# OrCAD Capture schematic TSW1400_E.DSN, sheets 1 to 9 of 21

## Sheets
1 BLOCK DIAGRAM: title: BLOCK DIAGRAM; rev: E; note: SCH, TSW1400 EVM
2 BUTTON, SWITCH, LEDS: size B; title: SWITCHES, LEDS, BUTTONS
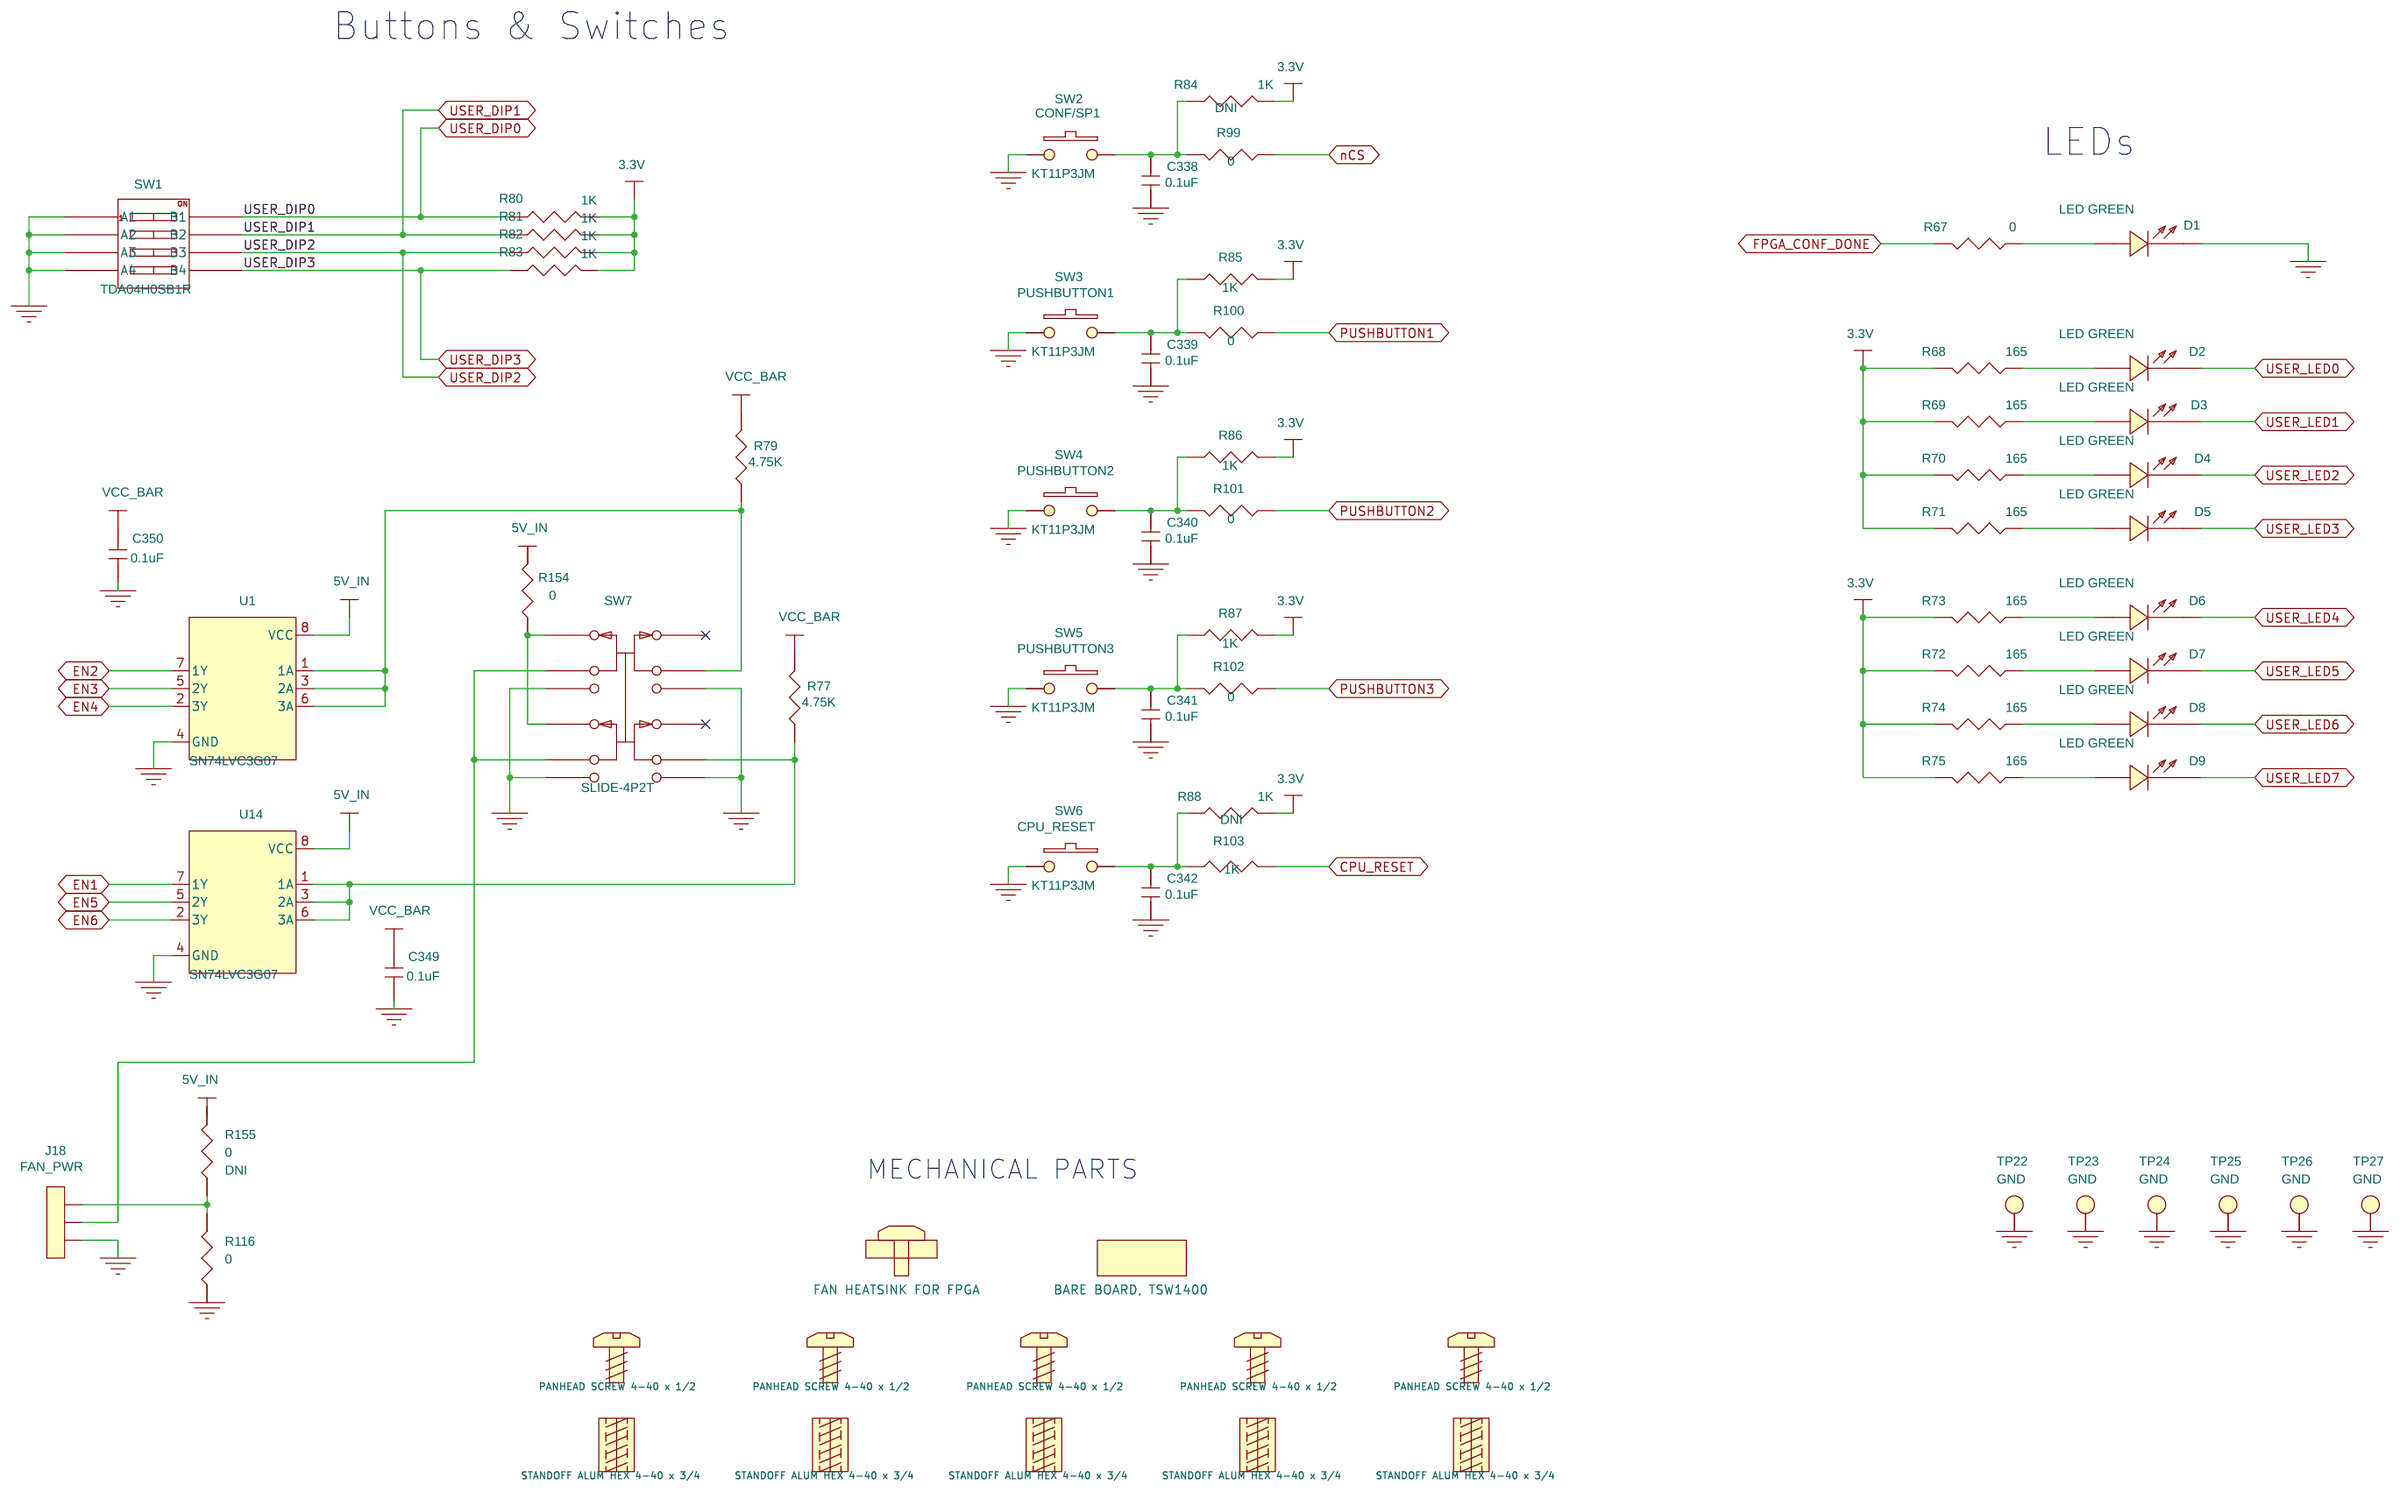
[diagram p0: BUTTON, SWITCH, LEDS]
3 ADC Interface, CMOS Header: size B; title: ADC INTERFACE & CMOS HEADER
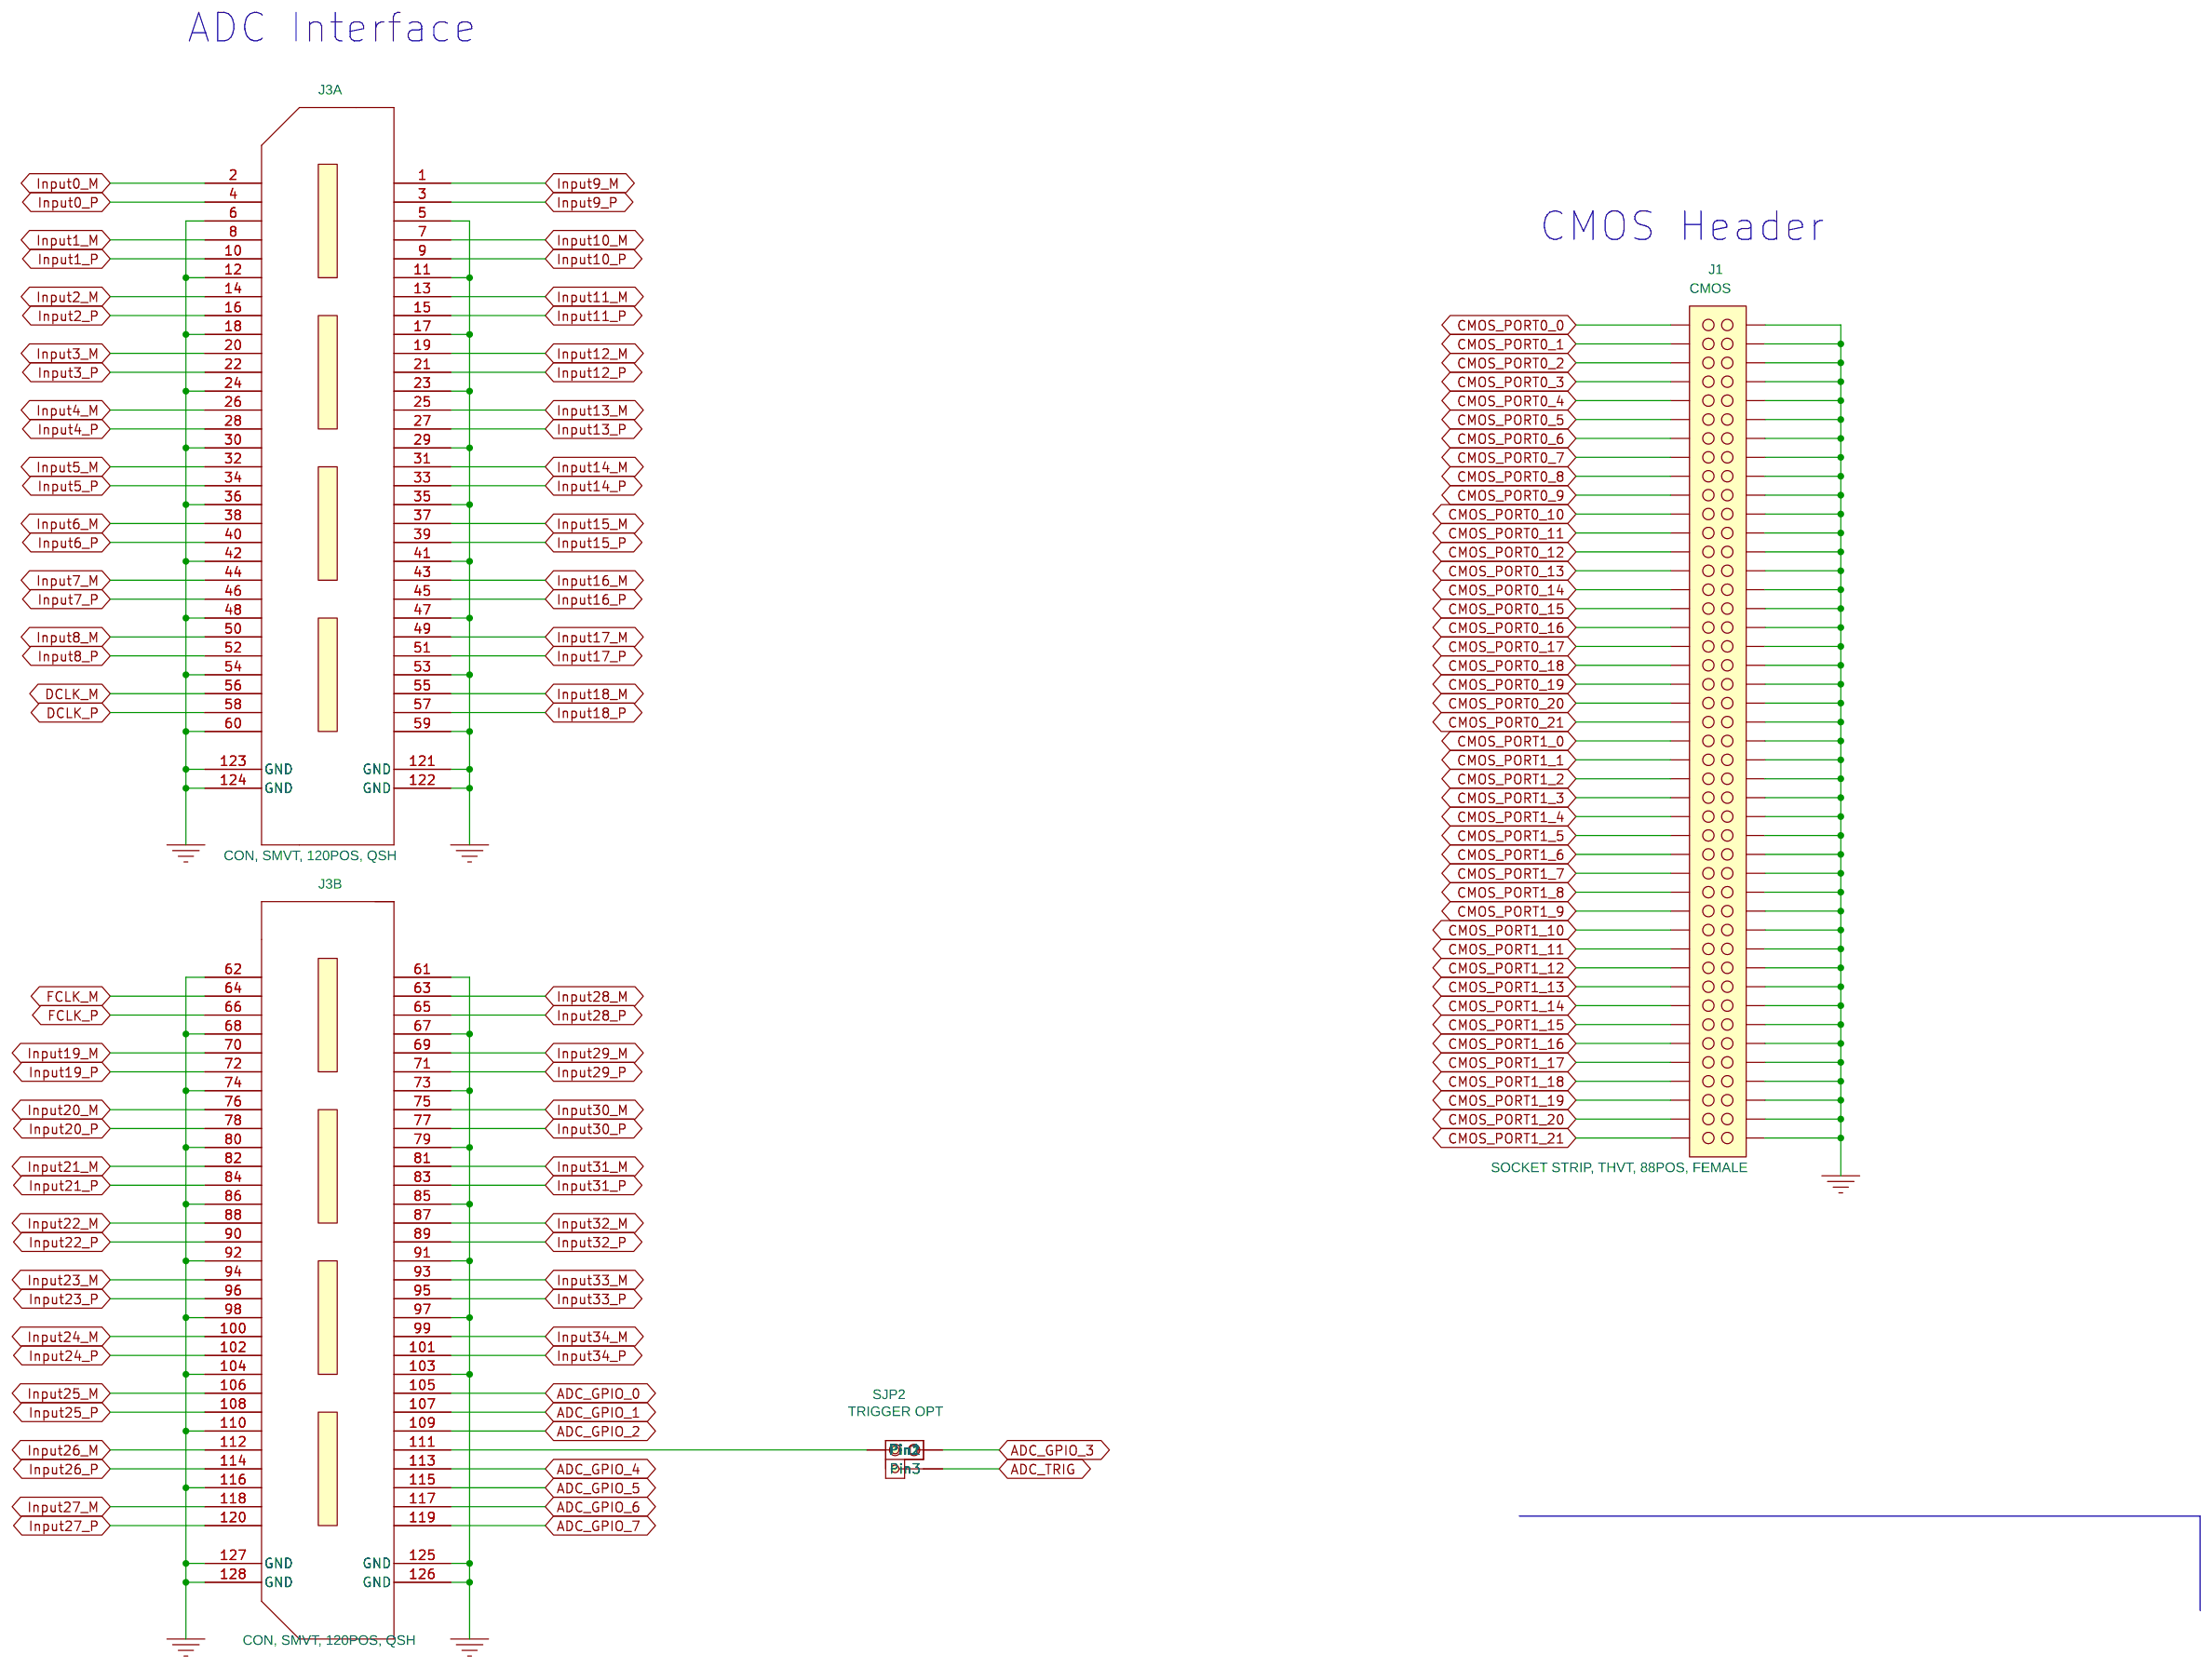
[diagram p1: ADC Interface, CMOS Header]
4 DAC Interface: size B; title: DAC Interface
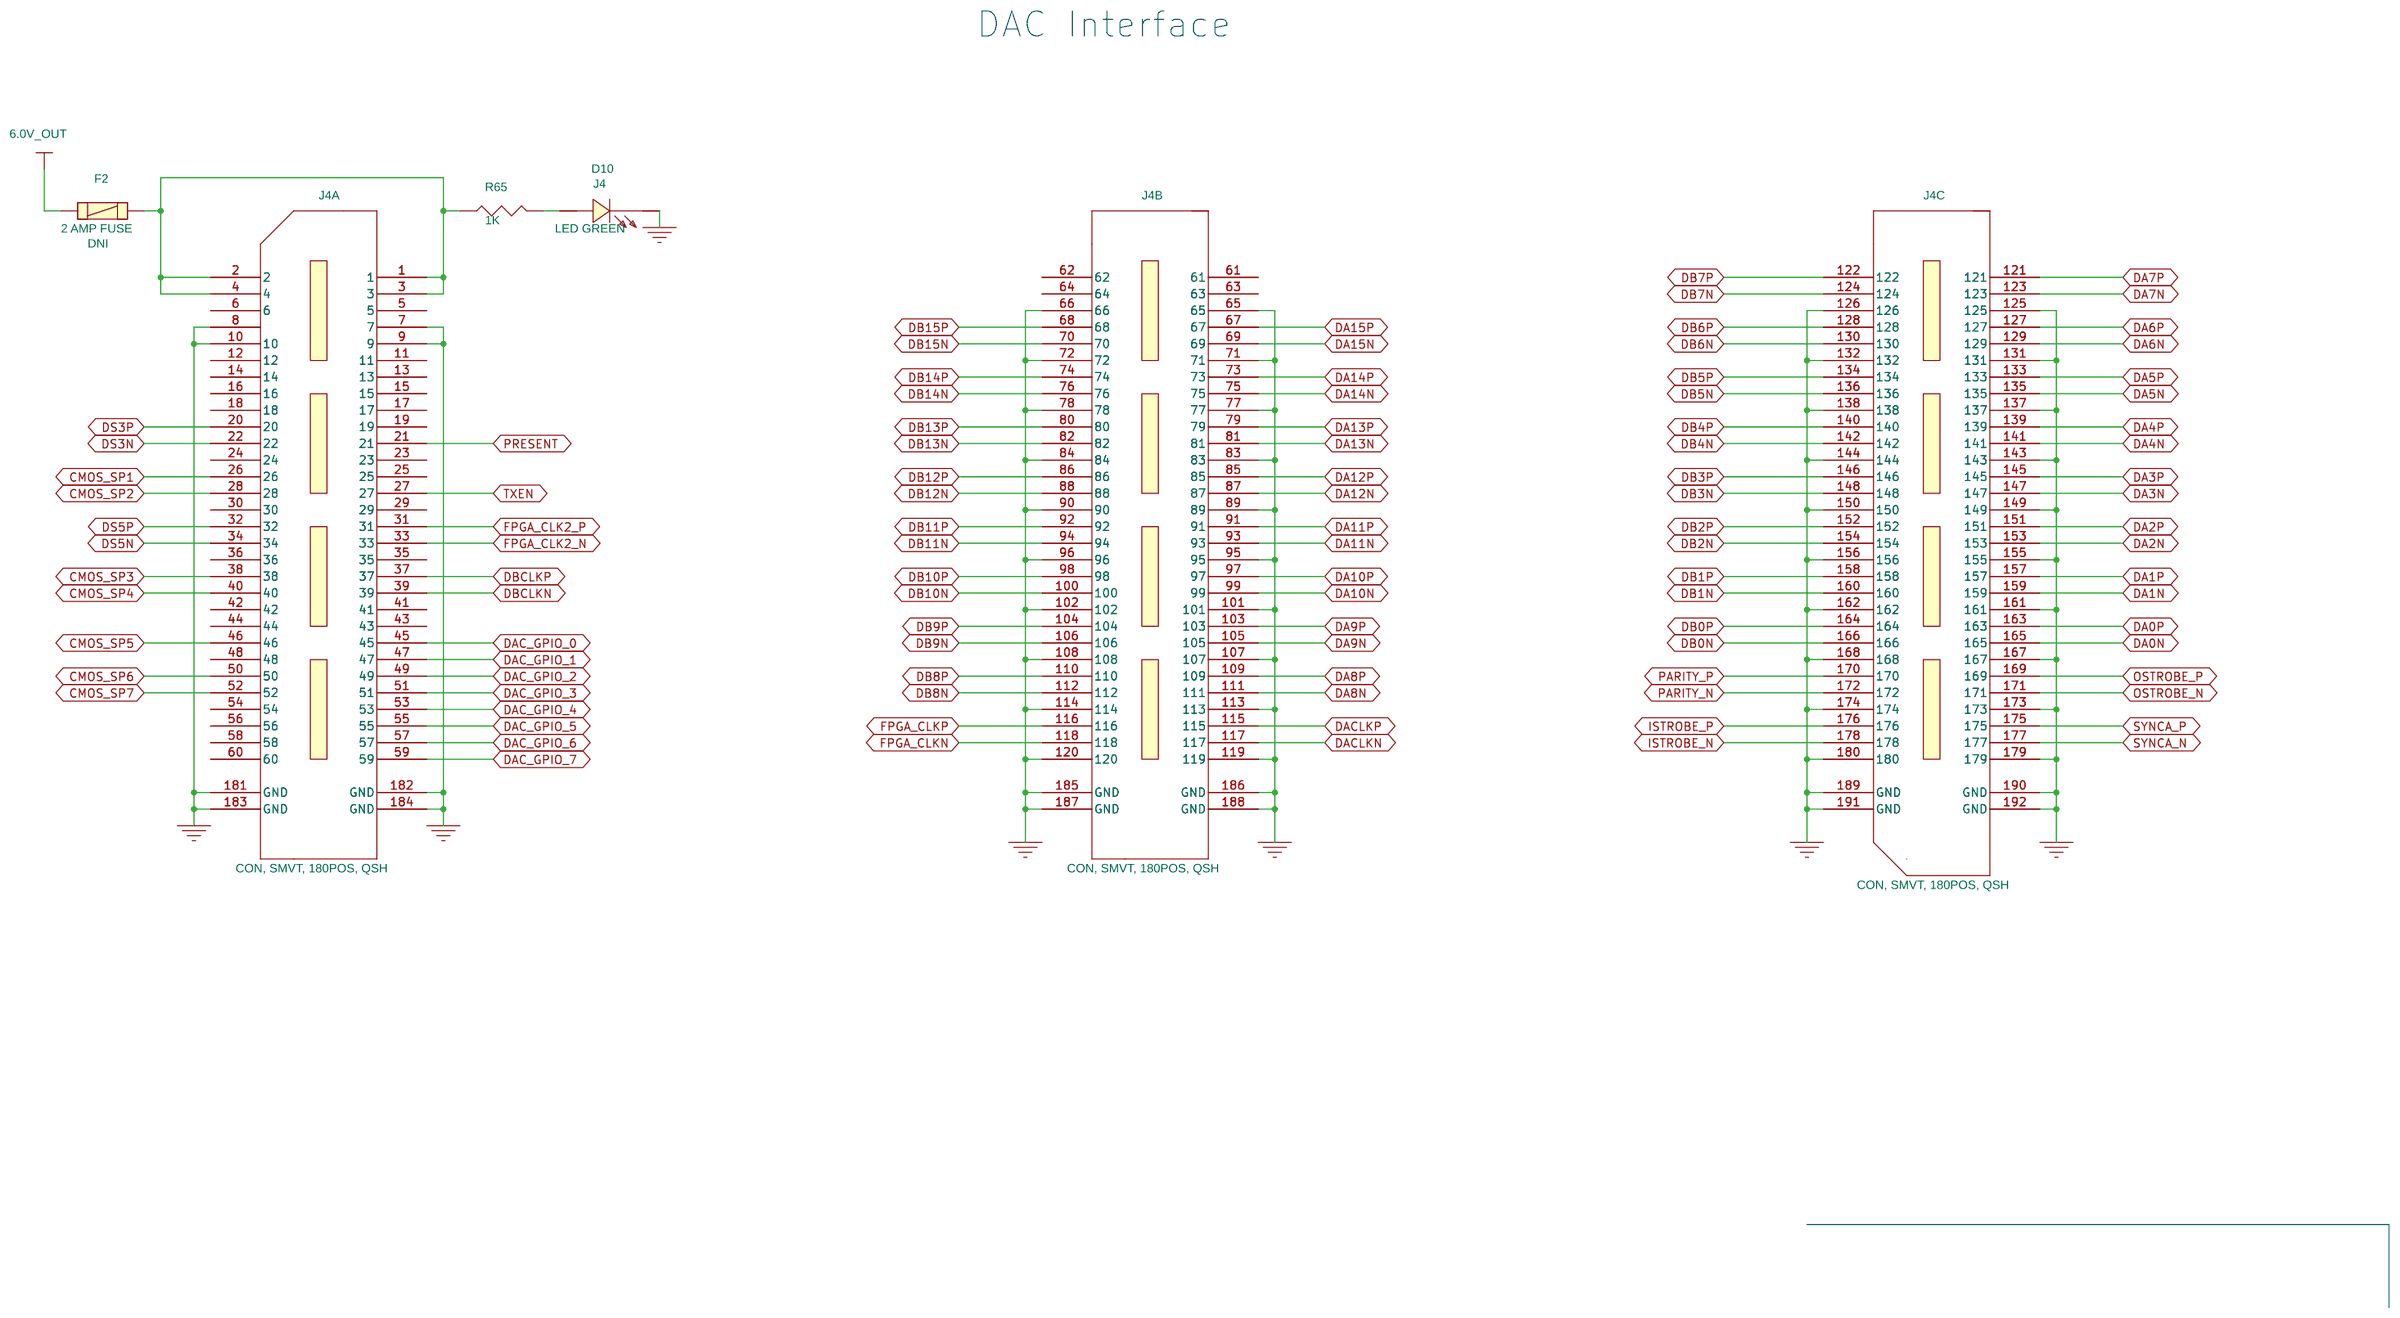
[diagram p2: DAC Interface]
5 USB: size B; title: USB
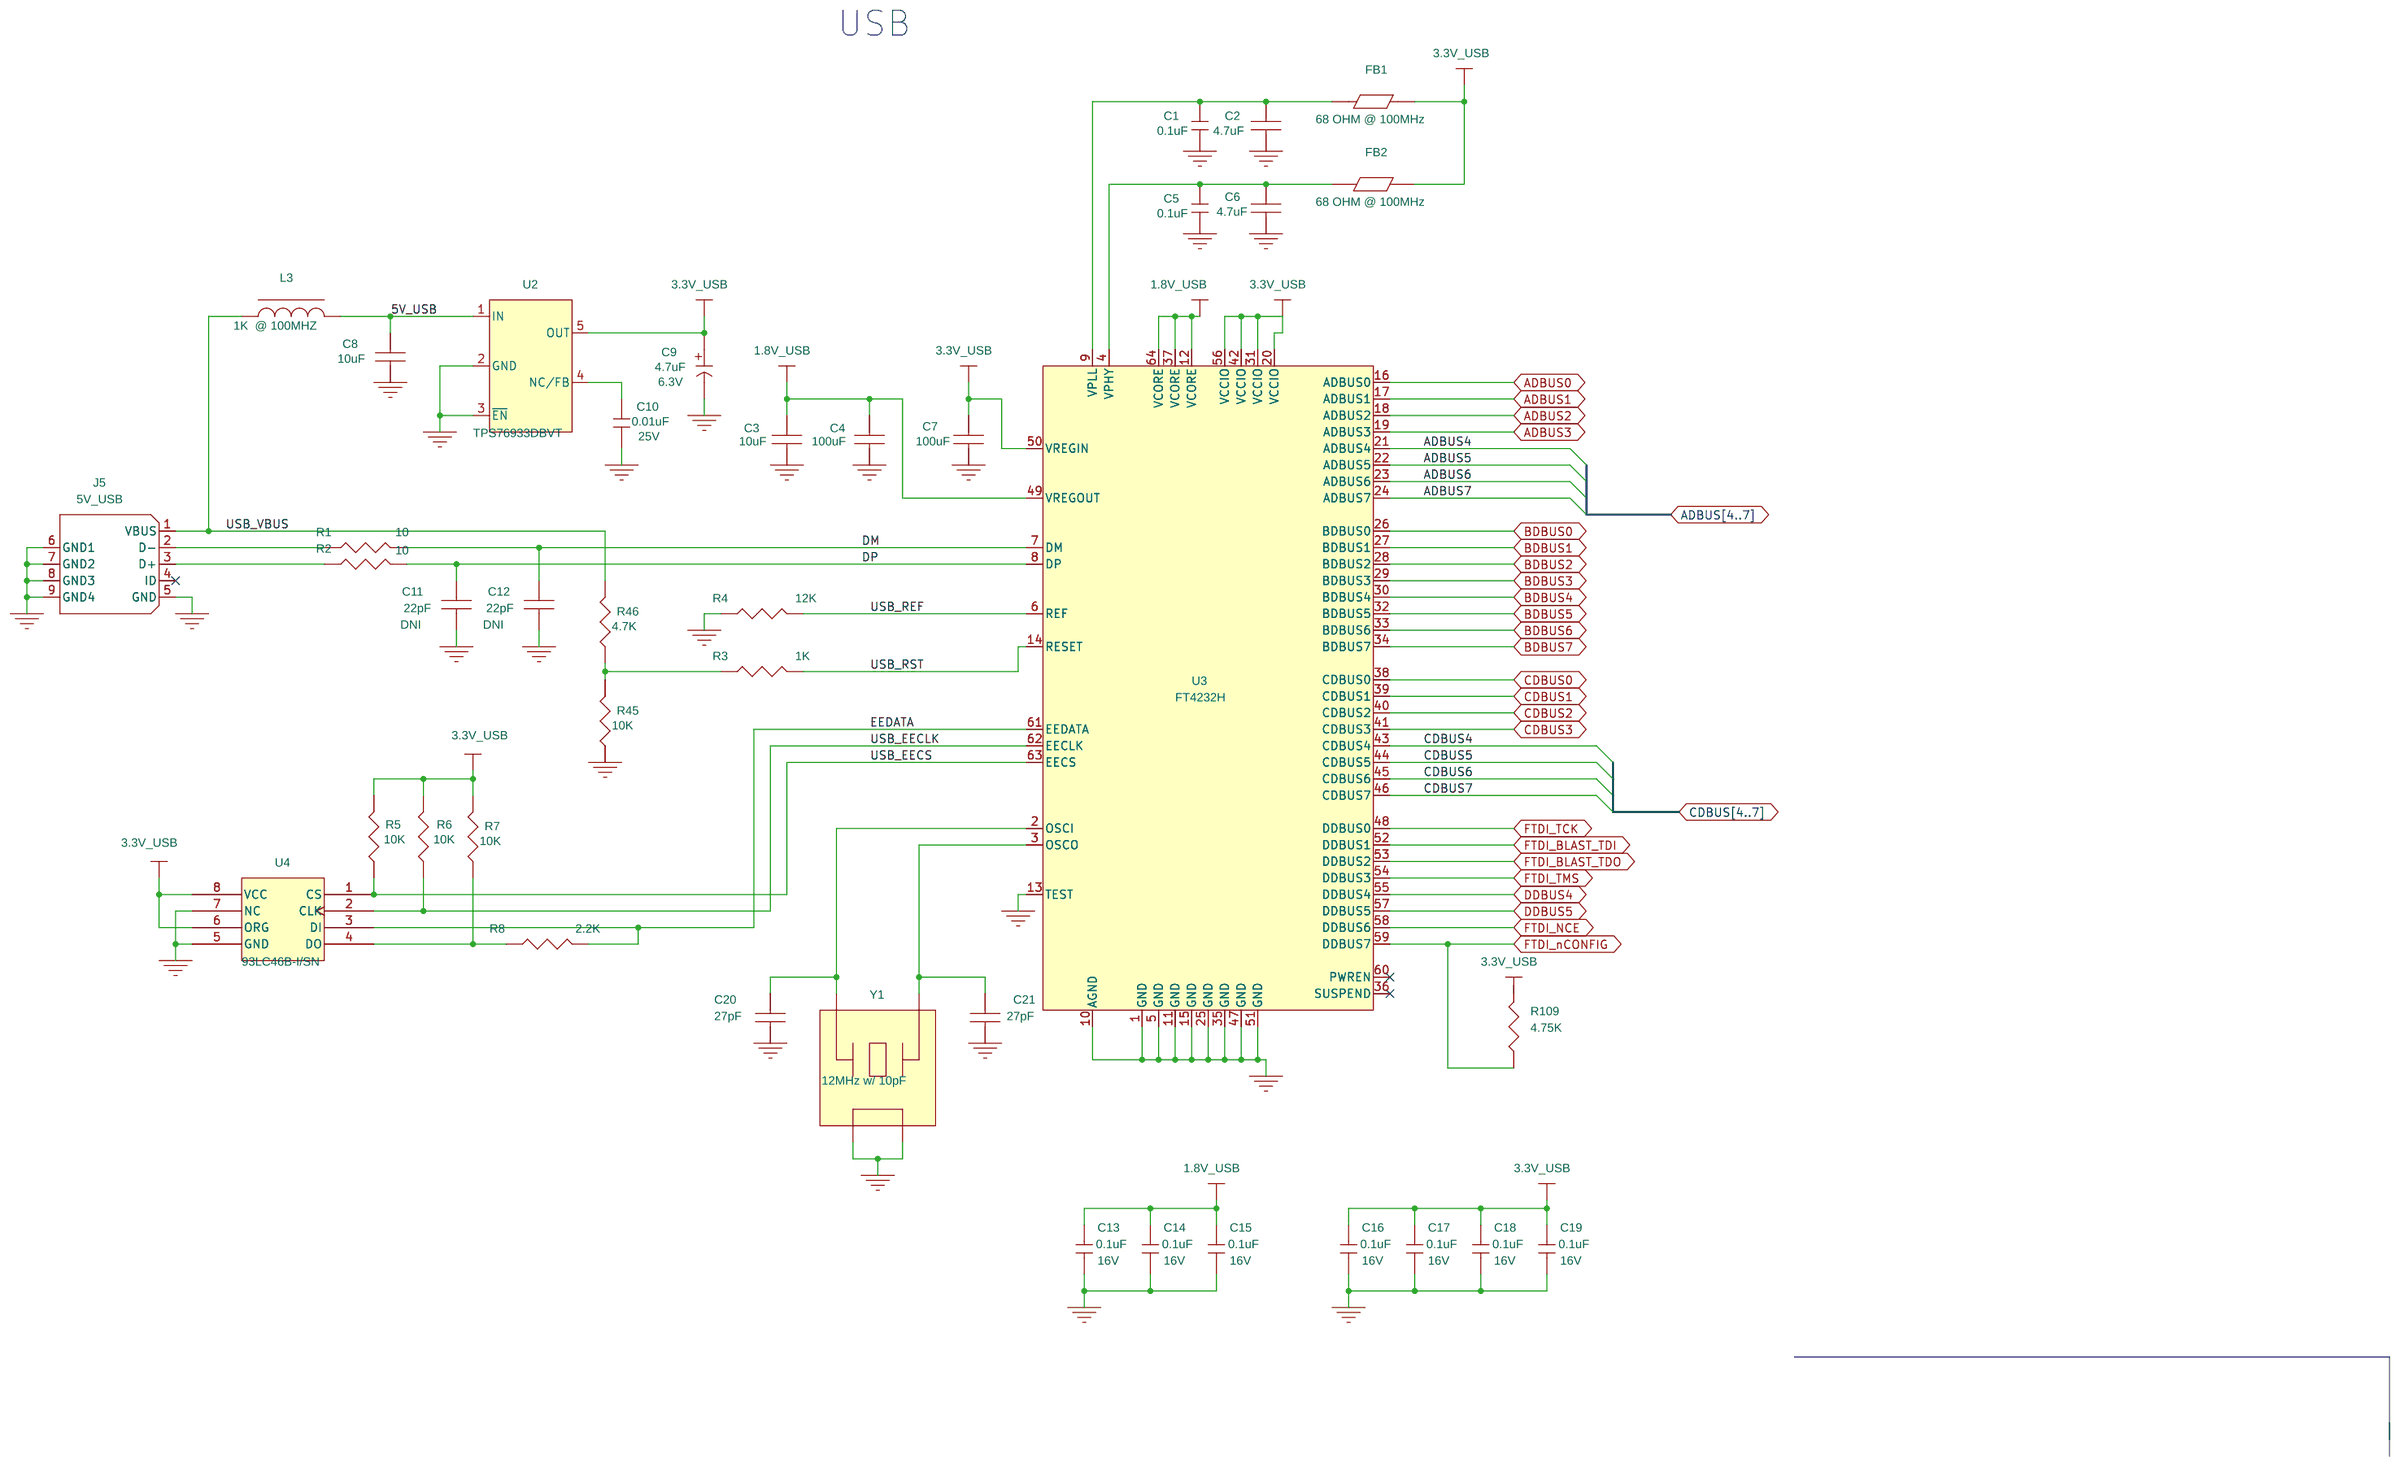
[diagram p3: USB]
6 DDR2 SO-DIMM: size C; title: DDR2 SO-DIMM
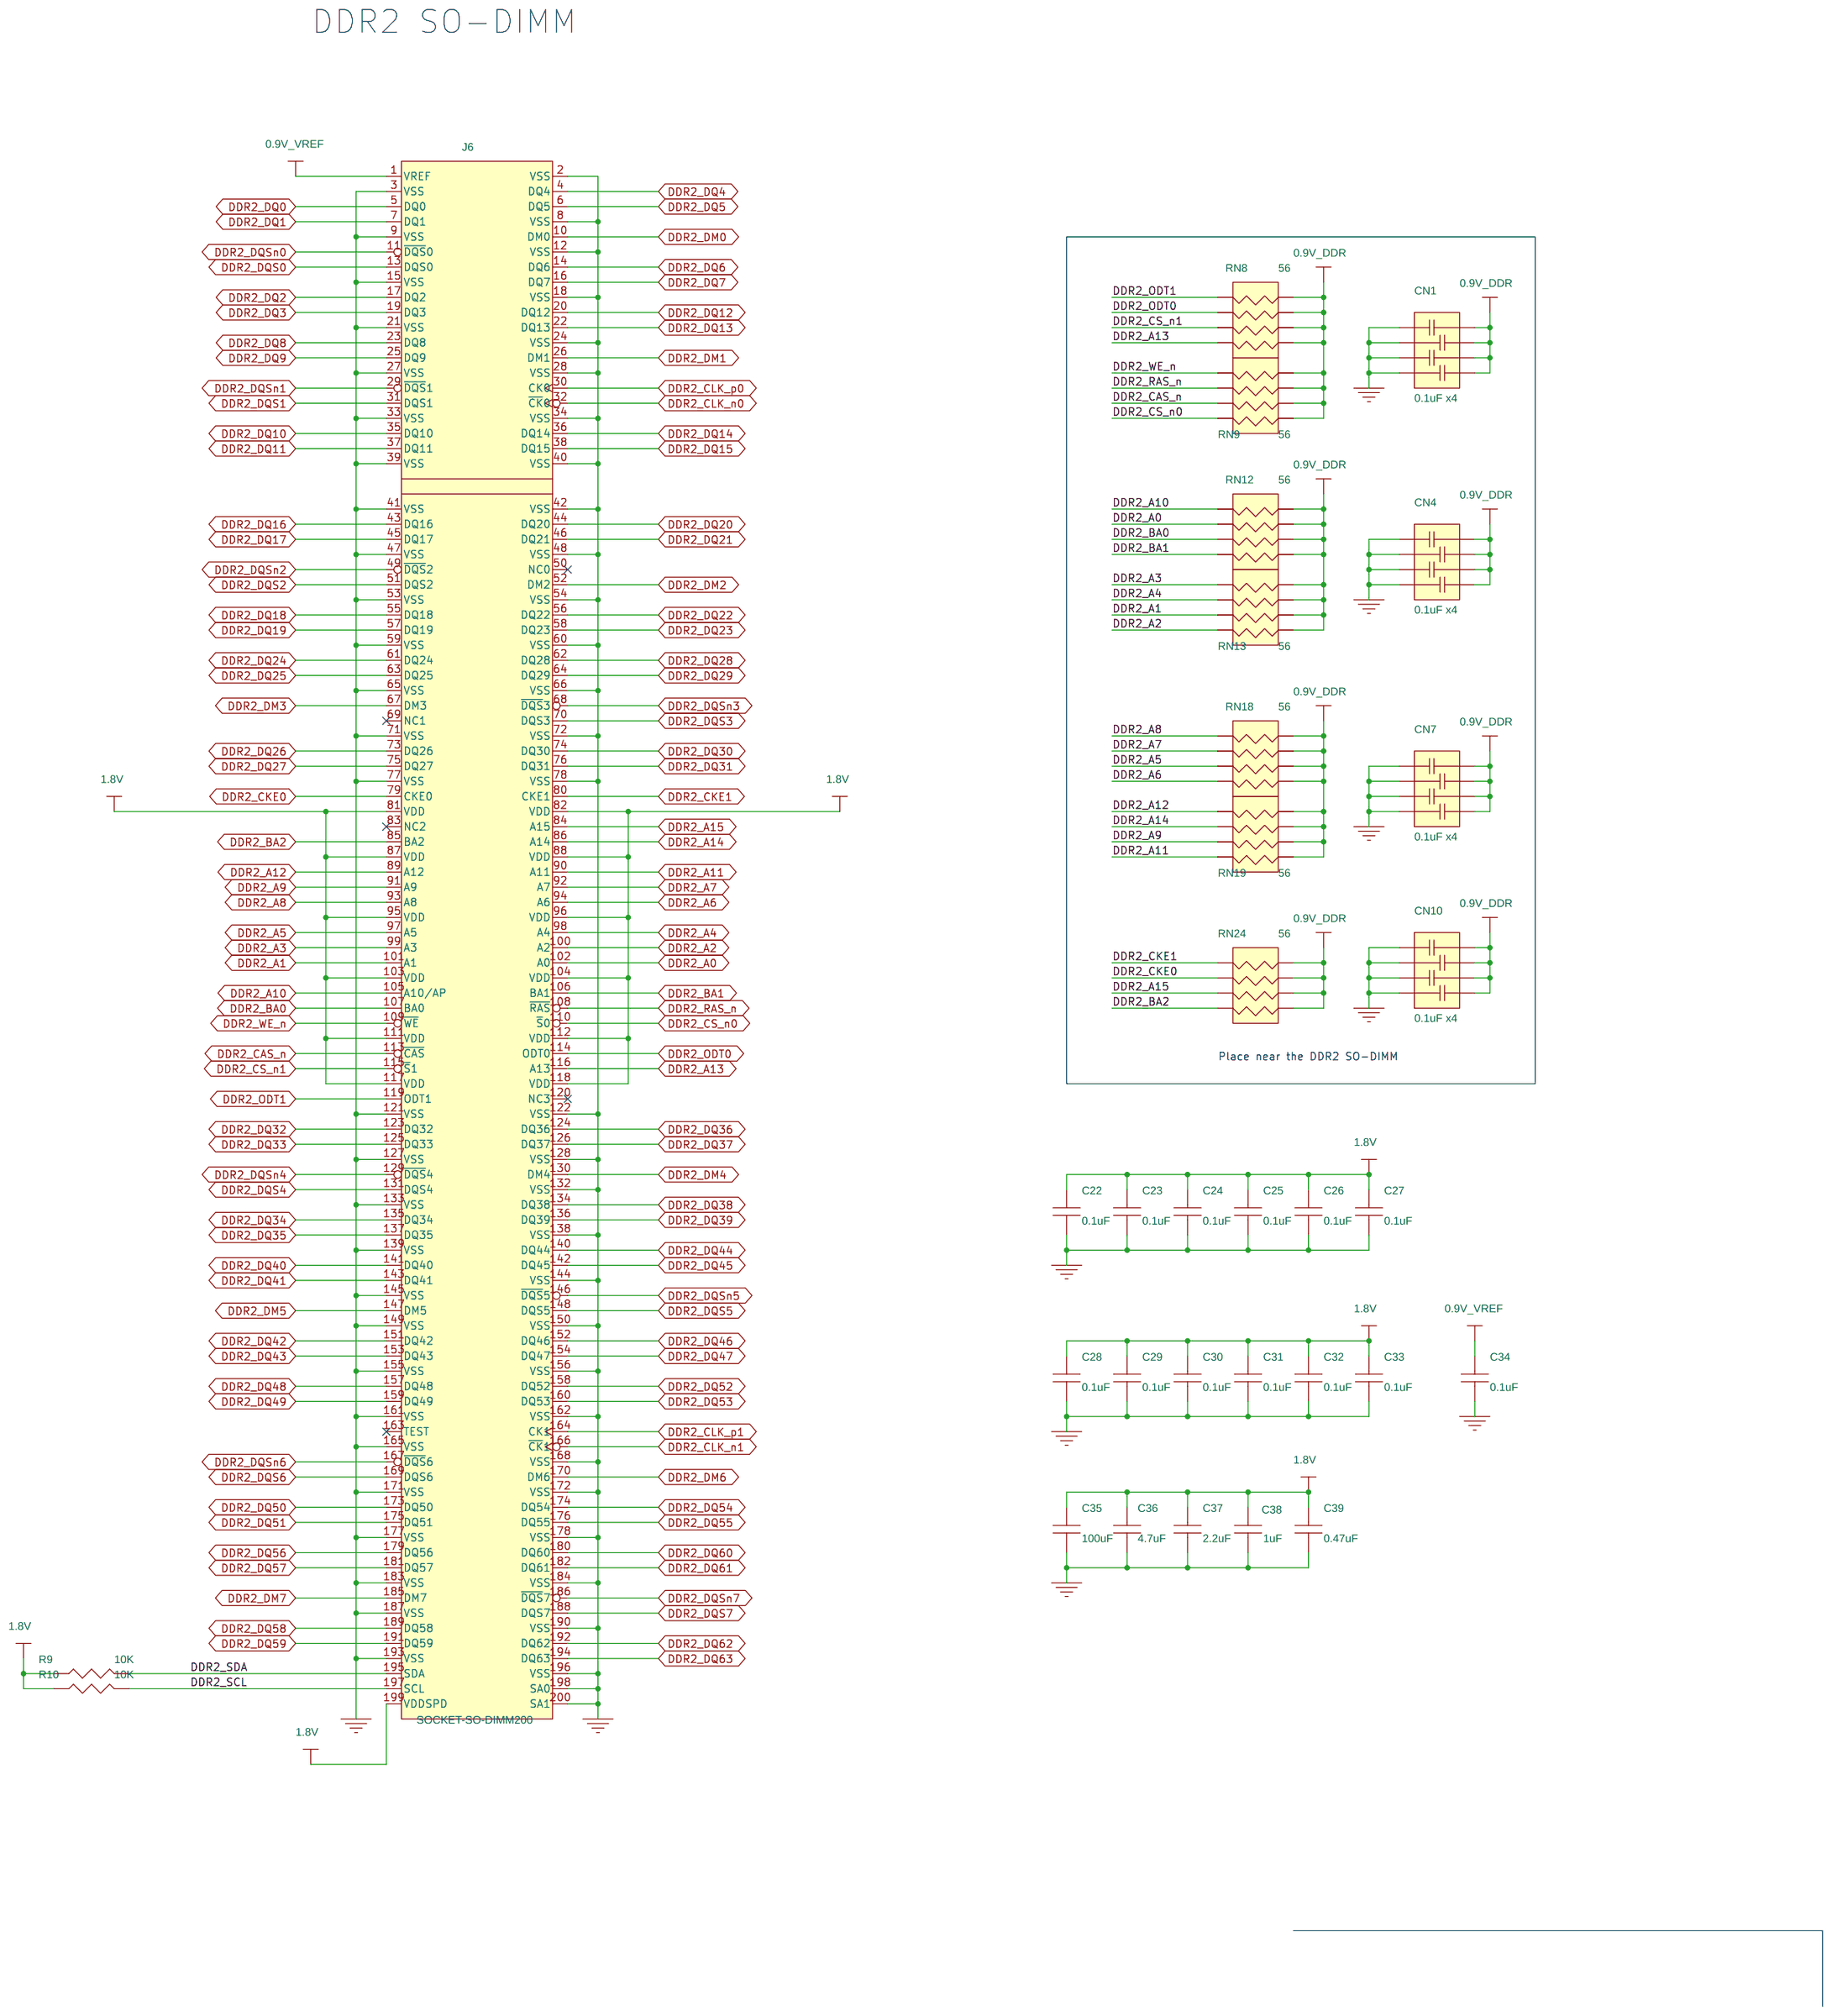
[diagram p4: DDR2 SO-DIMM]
7 Bank QL: size B; title: Bank QL
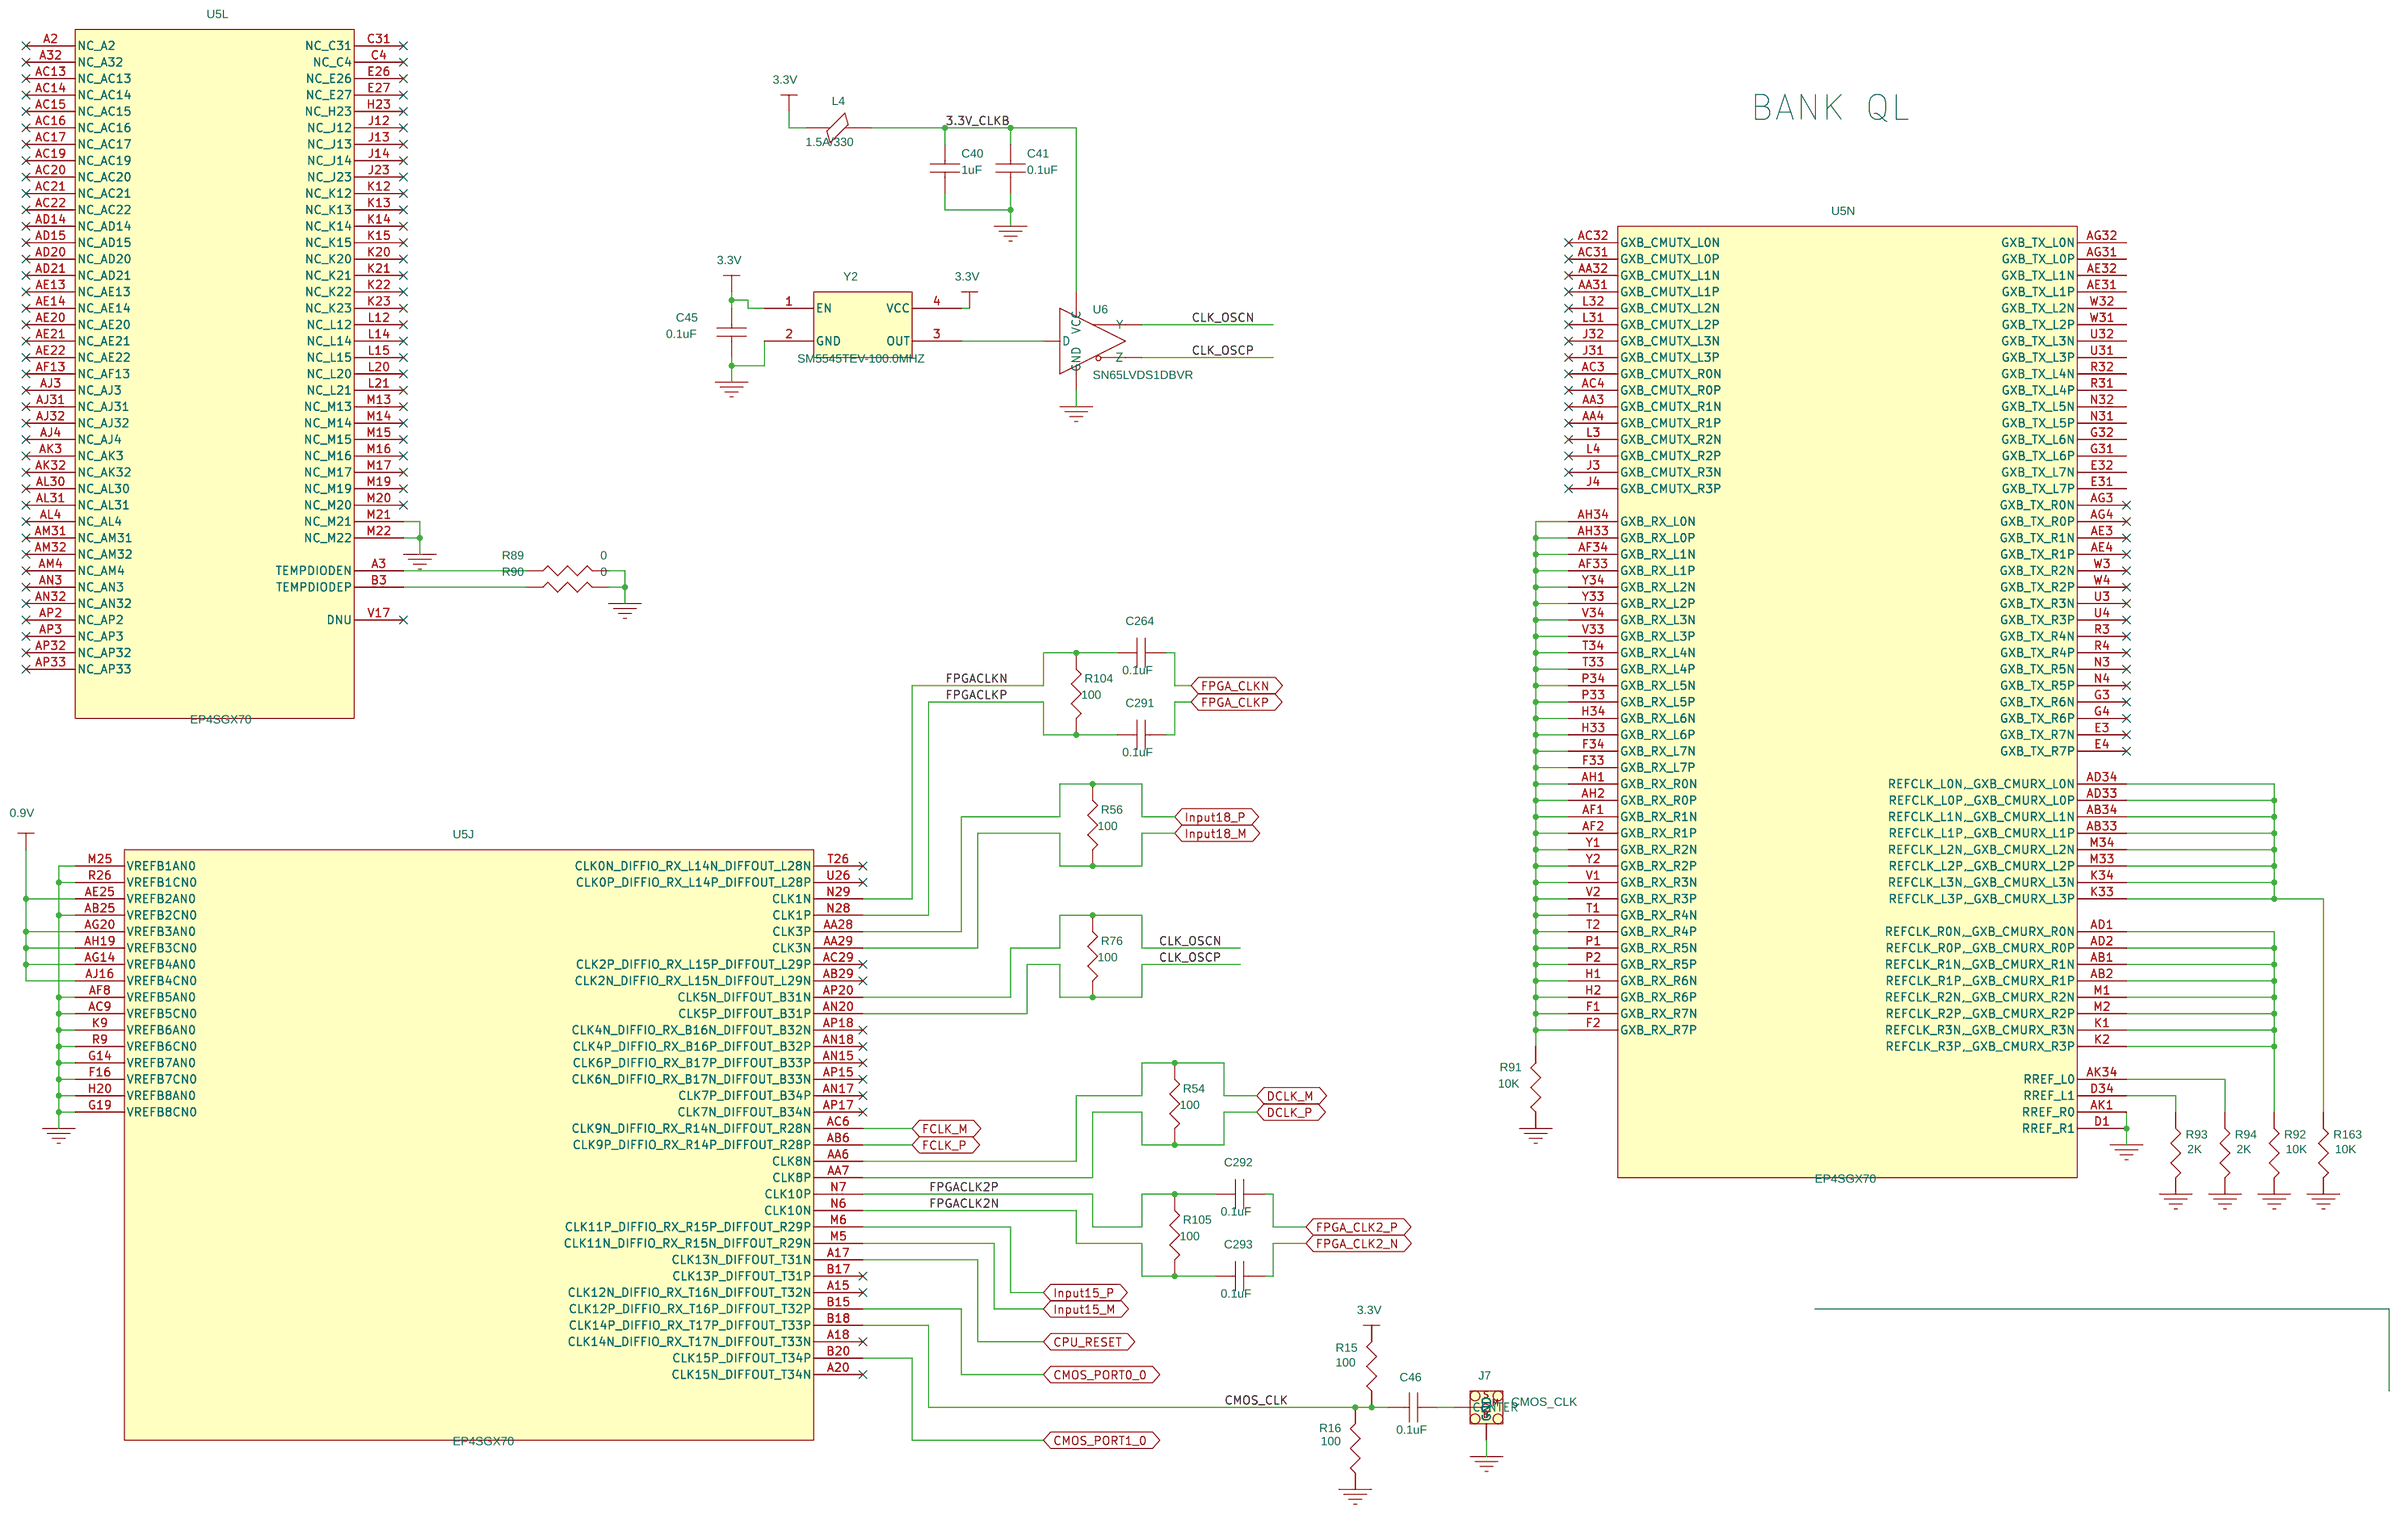
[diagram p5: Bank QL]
8 Bank 1: size B; title: Bank1
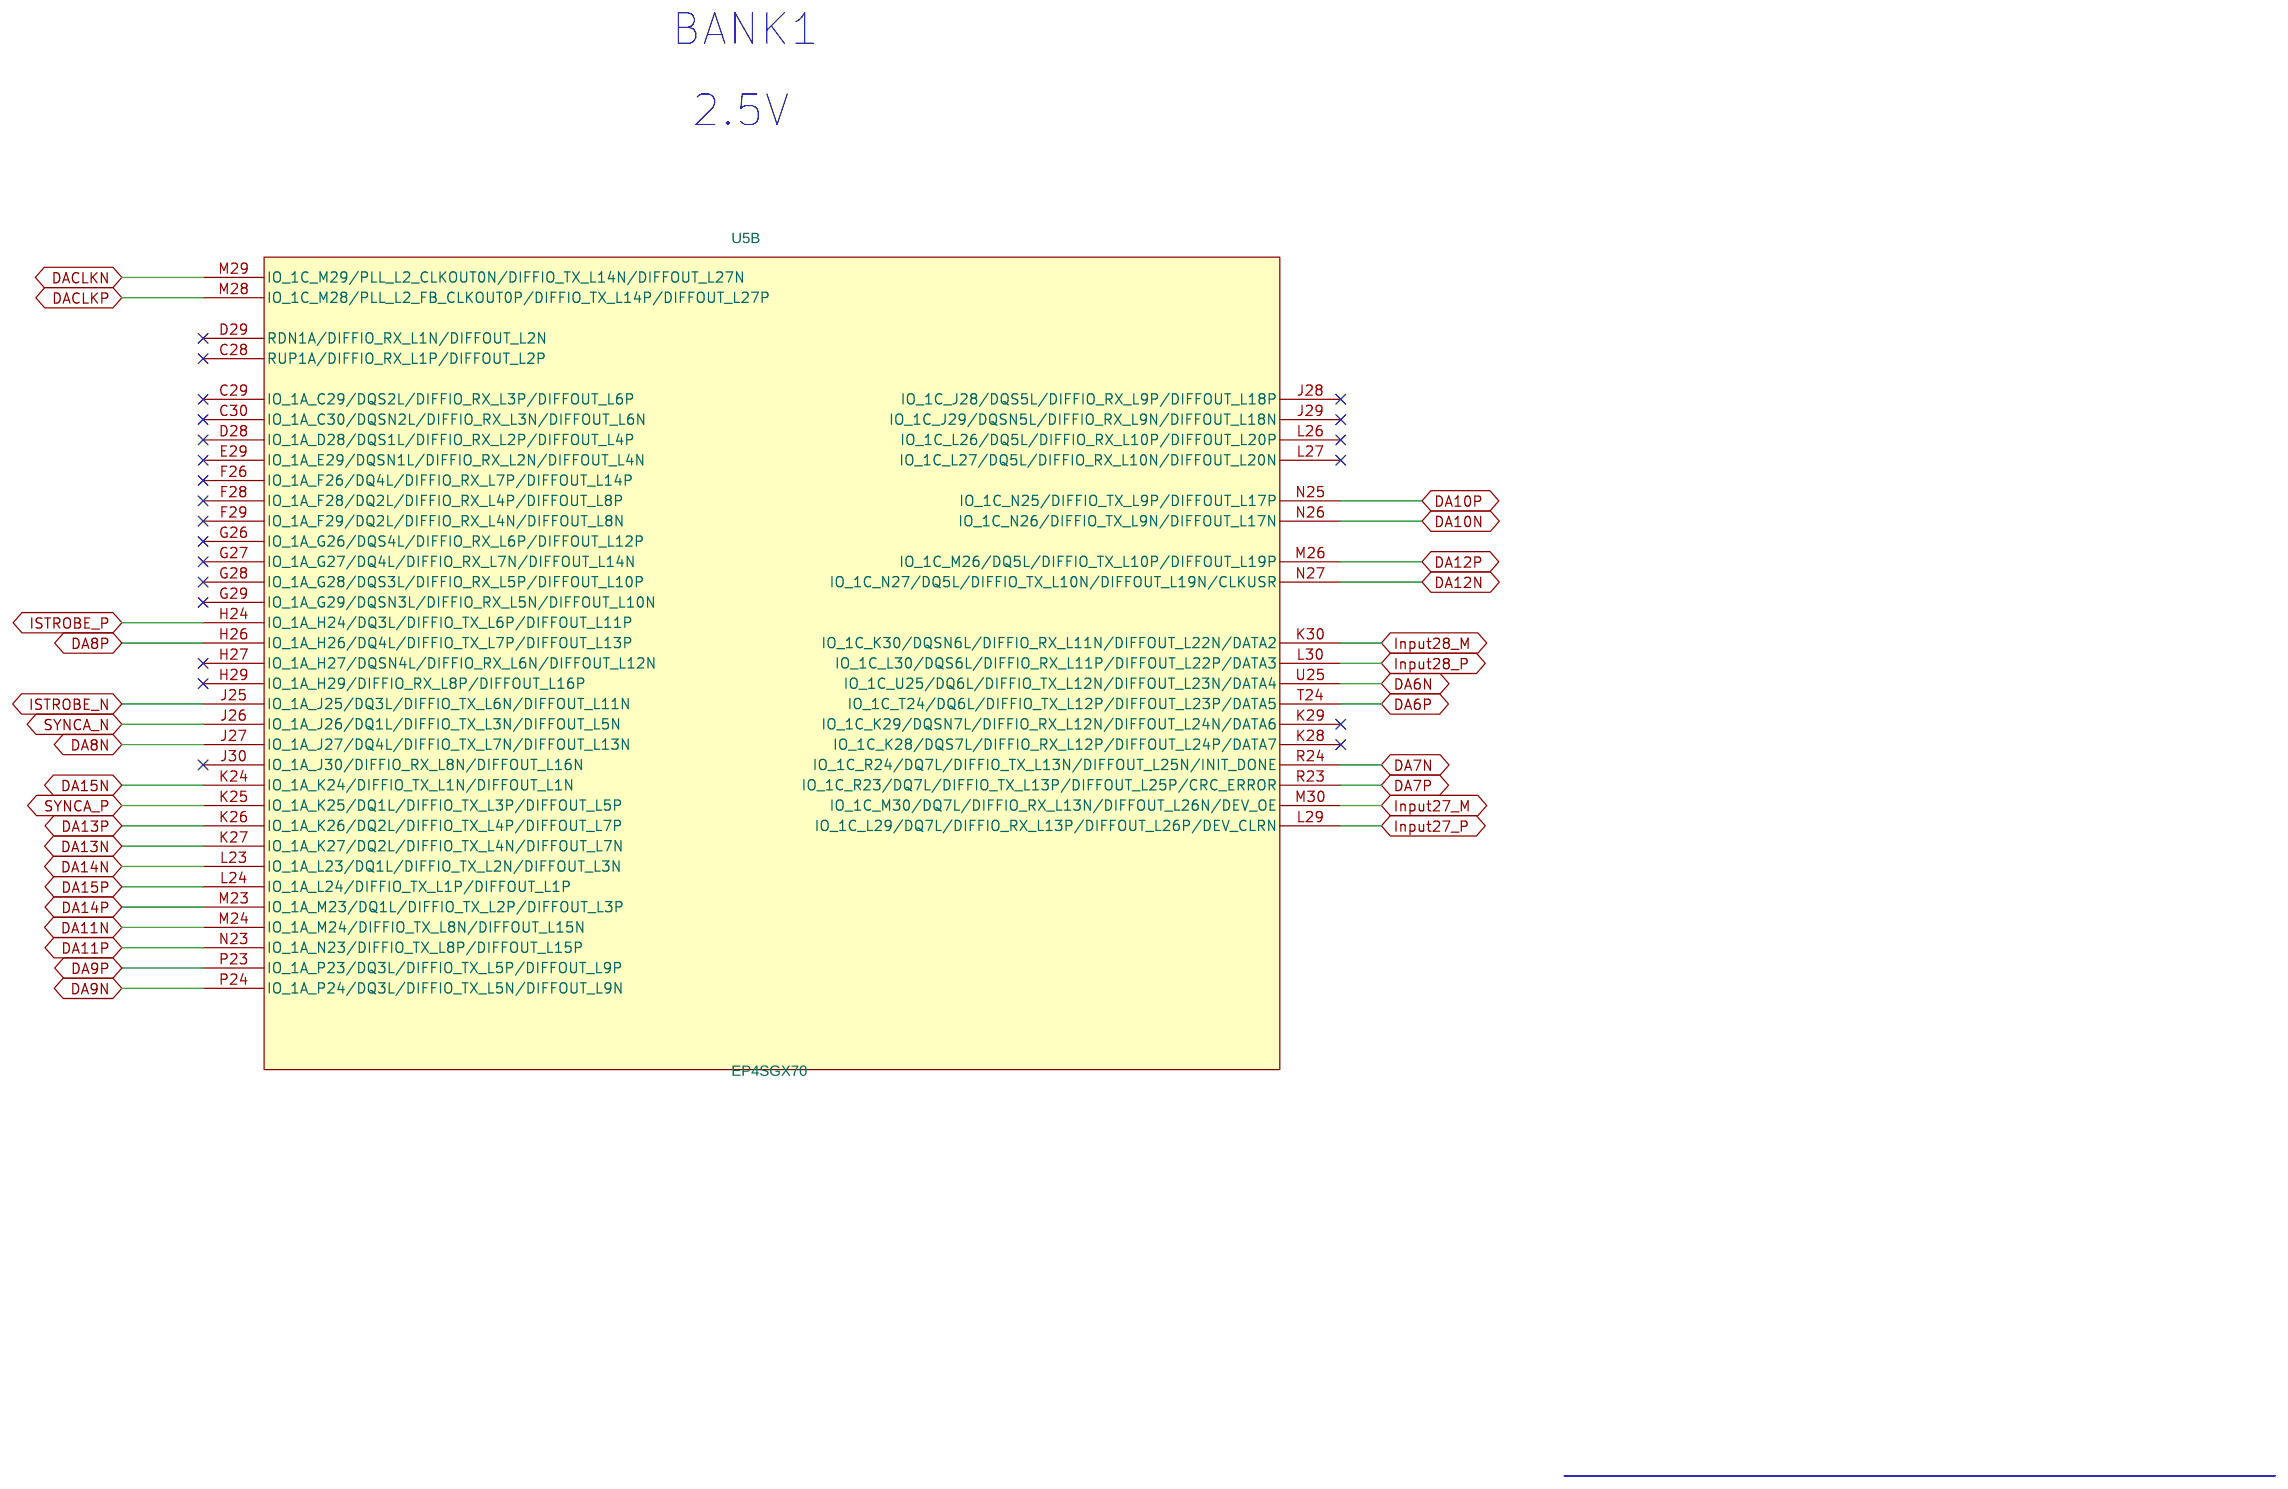
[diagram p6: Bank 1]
9 Bank 2: size B; title: Bank2
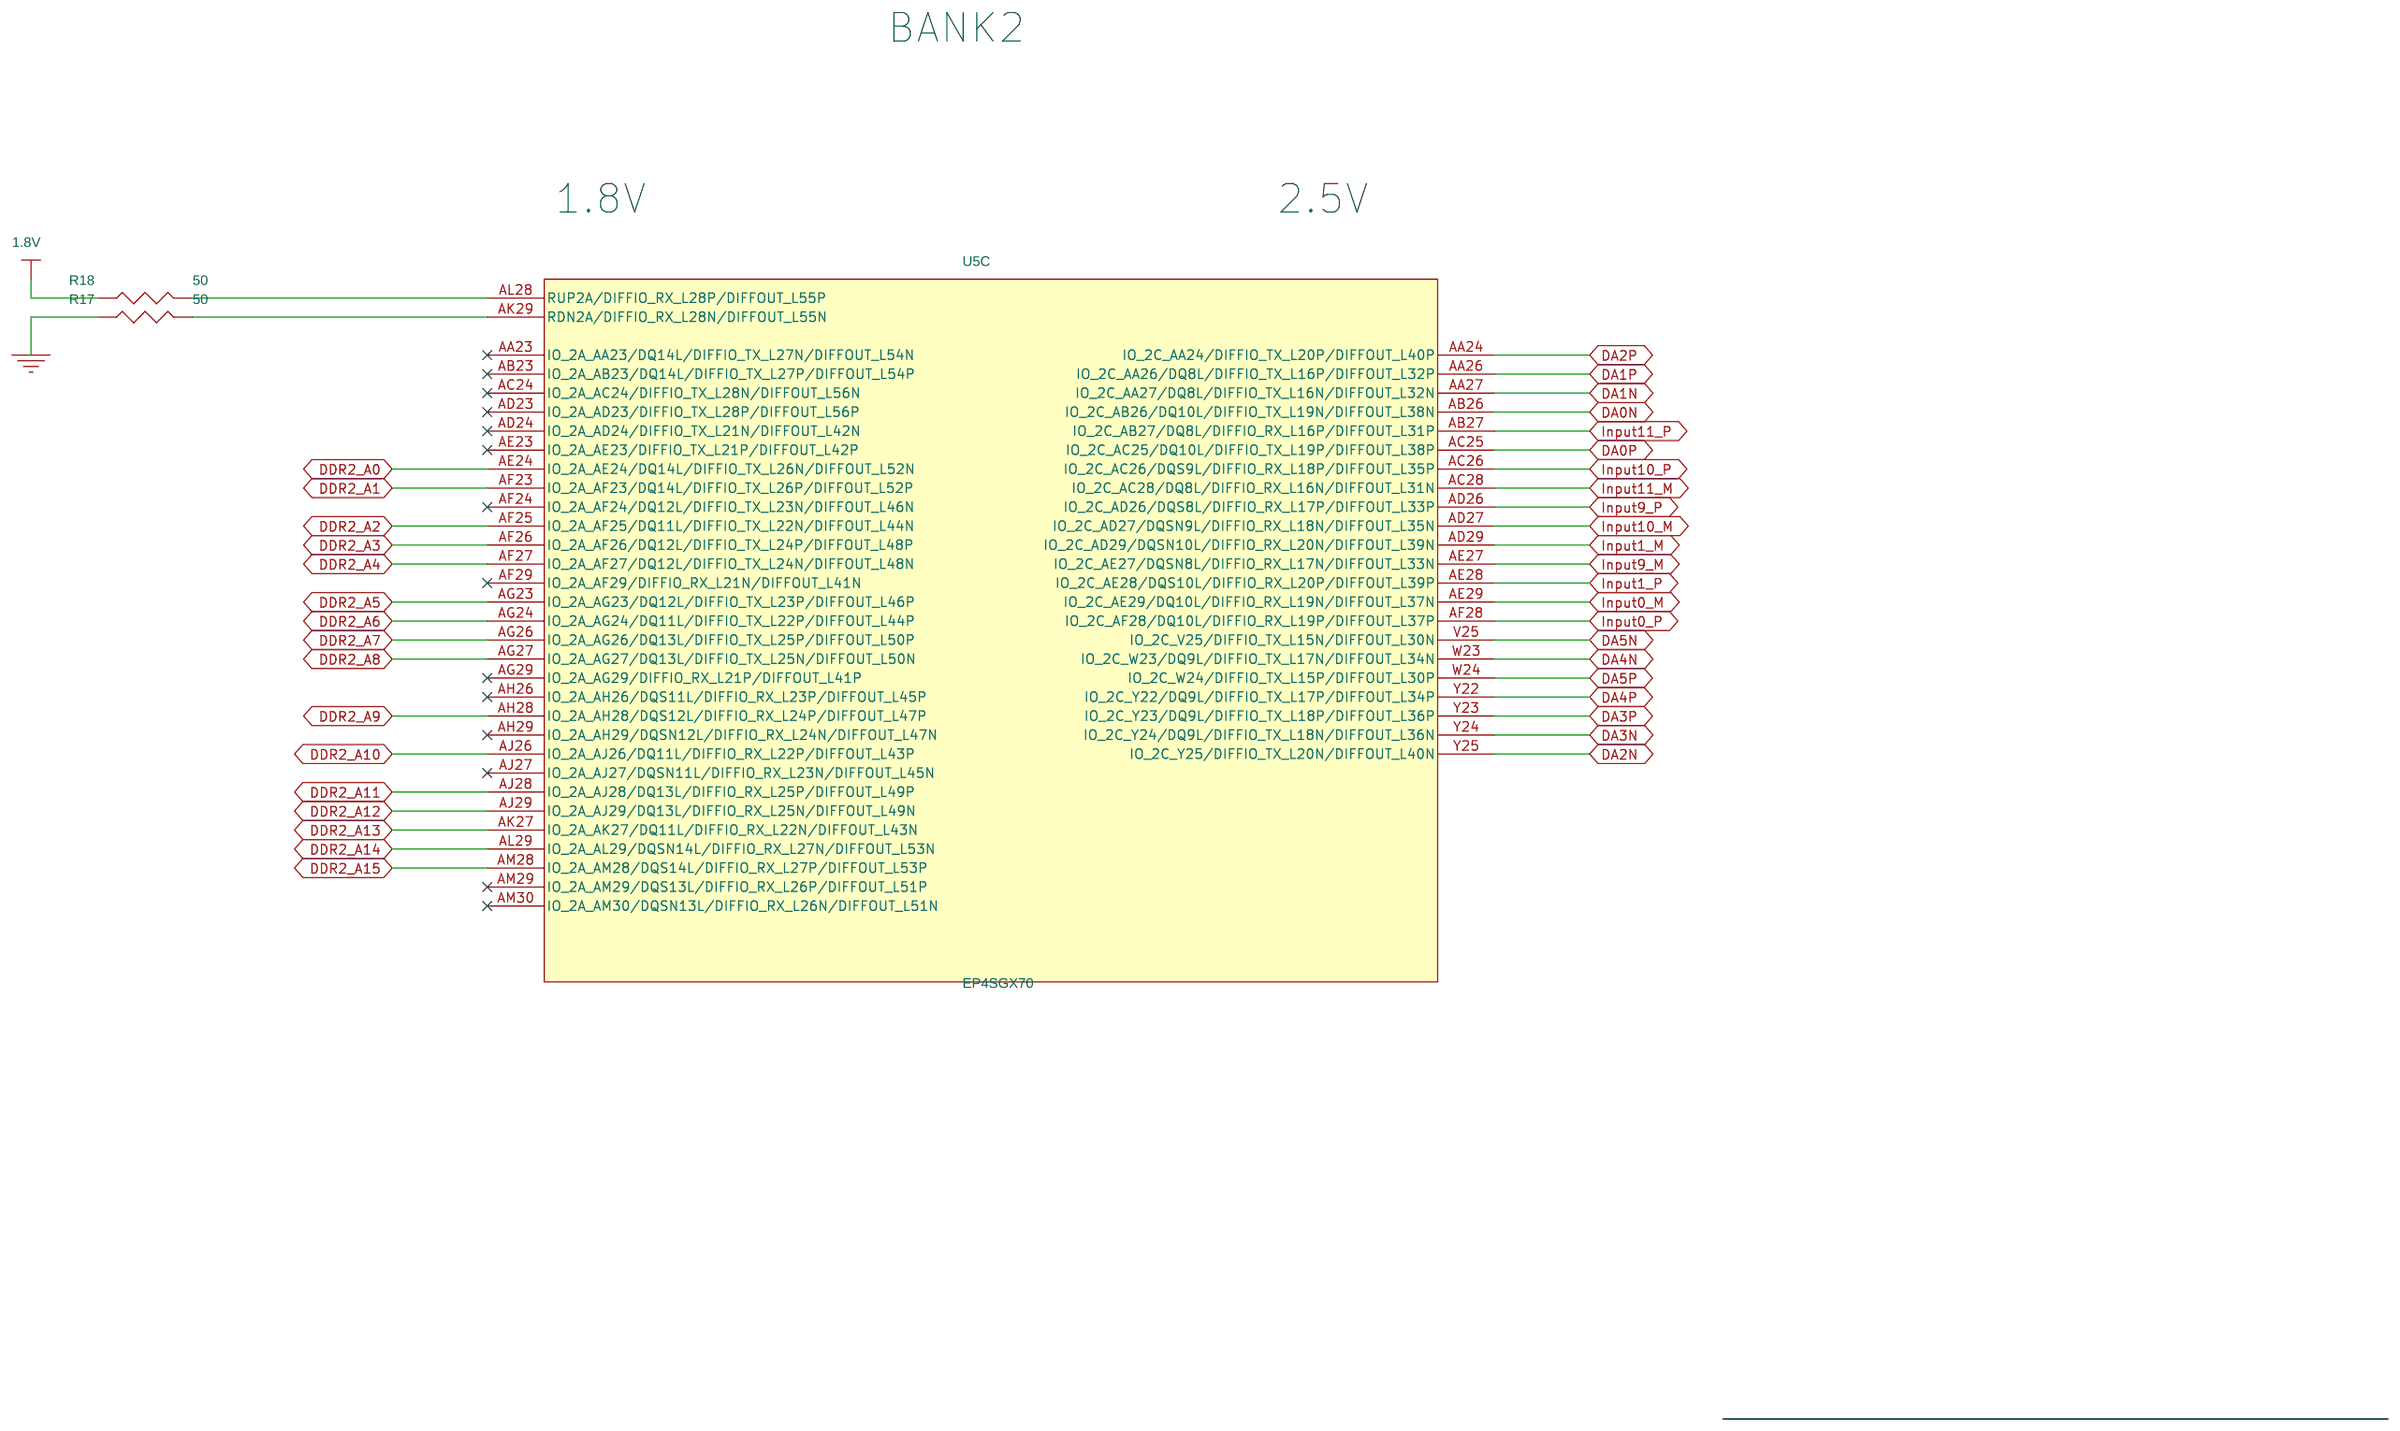
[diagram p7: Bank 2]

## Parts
sheet ADC Interface, CMOS Header
J1  SOCKET STRIP, THVT, 88POS, FEMALE  [HDR_THVT_2x44_100_F]
J3  CON, SMVT, 120POS, QSH  [CON_SMVT_120POS_QSH_SAMTEC_RT1]  (sections A,B)
SJP2  JUMPER_L_0603_SMT  [JUMPER_SMD_L_0603]
Z_SH-J6  SHUNT-JUMPER-0603  [0603]
sheet Bank 2
R17  50  [0402]
R18  50  [0402]
U5  EP4SGX70  [BGA_1152_39]  (sections A,B,C,D,E,F,G,H,I,J,K,L,M,N)
sheet Bank QL
C40  1uF  [0402]
C41  0.1uF  [0402]
C45  0.1uF  [0402]
C46  0.1uF  [0603]
C264  0.1uF  [0402]
C291  0.1uF  [0402]
C292  0.1uF  [0402]
C293  0.1uF  [0402]
J7  SMB_THVT_REC  [SMA_THVT_312x312]
L4  1.5A/330  [IND_0805]
R15  100  [0603]
R16  100  [0603]
R54  100  [0201]
R56  100  [0201]
R76  100  [0402]
R89  0  [0402]
R90  0  [0402]
R91  10K  [0402]
R92  10K  [0402]
R93  2K  [0402]
R94  2K  [0402]
R104  100  [0201]
R105  100  [0201]
R163  10K  [0402]
U6  SN65LVDS1DBVR  [SOP_5_118x67_37]
Y2  SM5545TEV-100.0MHZ  [OSC-3X5mm]
sheet BUTTON, SWITCH, LEDS
C338  0.1uF  [0603]
C339  0.1uF  [0603]
C340  0.1uF  [0603]
C341  0.1uF  [0603]
C342  0.1uF  [0603]
C349  0.1uF  [0402]
C350  0.1uF  [0402]
D1  LED GREEN  [LED_0805]
D2  LED GREEN  [LED_0805]
D3  LED GREEN  [LED_0805]
D4  LED GREEN  [LED_0805]
D5  LED GREEN  [LED_0805]
D6  LED GREEN  [LED_0805]
D7  LED GREEN  [LED_0805]
D8  LED GREEN  [LED_0805]
D9  LED GREEN  [LED_0805]
J18  HDR,  3POS, VT, .100, LOCK  [HDR_THVT_1x3_100_M_KEYED]
R67  0  [0402]
R68  165  [0603]
R69  165  [0603]
R70  165  [0603]
R71  165  [0603]
R72  165  [0603]
R73  165  [0603]
R74  165  [0603]
R75  165  [0603]
R77  4.75K  [0402]
R79  4.75K  [0402]
R80  1K  [0402]
R81  1K  [0402]
R82  1K  [0402]
R83  1K  [0402]
R84  1K  [0402]
R85  1K  [0402]
R86  1K  [0402]
R87  1K  [0402]
R88  1K  [0402]
R99  0  [0402]
R100  0  [0402]
R101  0  [0402]
R102  0  [0402]
R103  1K  [0402]
R116  0  [0603]
R154  0  [0603]
R155  0  [0603]
SW1  TDA04H0SB1R  [SW-SMD-8]
SW2  KT11P3JM  [SW_SMVT_SPST_4]
SW3  KT11P3JM  [SW_SMVT_SPST_4]
SW4  KT11P3JM  [SW_SMVT_SPST_4]
SW5  KT11P3JM  [SW_SMVT_SPST_4]
SW6  KT11P3JM  [SW_SMVT_SPST_4]
SW7  SLIDE-4P2T  [SW_THVT_4PDT_SLIDE_12]
TP22  Testloop_Black  [TP_THVT_060_RND]
TP23  Testloop_Black  [TP_THVT_060_RND]
TP24  Testloop_Black  [TP_THVT_060_RND]
TP25  Testloop_Black  [TP_THVT_060_RND]
TP26  Testloop_Black  [TP_THVT_060_RND]
TP27  Testloop_Black  [TP_THVT_060_RND]
U1  SN74LVC3G07  [VSSOP_8_83X94_0P5MM]
U14  SN74LVC3G07  [VSSOP_8_83X94_0P5MM]
Z_BOARD1  BARE BOARD, TSW1400
Z_FANHEATSINK  FAN HEATSINK FOR FPGA
Z_STANDOFF1  STANDOFF ALUM HEX 4-40 x 3/4
Z_STANDOFF2  STANDOFF ALUM HEX 4-40 x 3/4
Z_STANDOFF3  STANDOFF ALUM HEX 4-40 x 3/4
Z_STANDOFF4  STANDOFF ALUM HEX 4-40 x 3/4
Z_STANDOFF5  STANDOFF ALUM HEX 4-40 x 3/4
Z_STANDOFF SCREW1  PANHEAD SCREW 4-40 x 1/2
Z_STANDOFF SCREW2  PANHEAD SCREW 4-40 x 1/2
Z_STANDOFF SCREW3  PANHEAD SCREW 4-40 x 1/2
Z_STANDOFF SCREW4  PANHEAD SCREW 4-40 x 1/2
Z_STANDOFF SCREW5  PANHEAD SCREW 4-40 x 1/2
sheet DAC Interface
D10  LED GREEN  [LED_0805]
F2  2 AMP FUSE  [FUSE_SM_NANO]
J4  CON, SMVT, 180POS, QSH  [CON_SMVT_180POS_QSH_SAMTEC_RT1]  (sections A,B,C)
R65  1K  [0402]
sheet DDR2 SO-DIMM
C22  0.1uF  [0402]
C23  0.1uF  [0402]
C24  0.1uF  [0402]
C25  0.1uF  [0402]
C26  0.1uF  [0402]
C27  0.1uF  [0402]
C28  0.1uF  [0402]
C29  0.1uF  [0402]
C30  0.1uF  [0402]
C31  0.1uF  [0402]
C32  0.1uF  [0402]
C33  0.1uF  [0402]
C34  0.1uF  [0402]
C35  100uF  [1210]
C36  4.7uF  [0603]
C37  2.2uF  [0603]
C38  1uF  [0402]
C39  0.47uF  [0402]
CN1  0.1uF x4  [CA-AVE-0603-8]
CN4  0.1uF x4  [CA-AVE-0603-8]
CN7  0.1uF x4  [CA-AVE-0603-8]
CN10  0.1uF x4  [CA-AVE-0603-8]
J6  SOCKET-SO-DIMM200  [SOCKET-SO-DIMM200]
R9  10K  [0402]
R10  10K  [0402]
RN8  56  [RA-VEX-0402-8]
RN9  56  [RA-VEX-0402-8]
RN12  56  [RA-VEX-0402-8]
RN13  56  [RA-VEX-0402-8]
RN18  56  [RA-VEX-0402-8]
RN19  56  [RA-VEX-0402-8]
RN24  56  [RA-VEX-0402-8]
sheet USB
C1  0.1uF  [0603]
C2  4.7uF  [0603]
C3  10uF  [0603]
C4  100uF  [1206]
C5  0.1uF  [0603]
C6  4.7uF  [0603]
C7  100uF  [1206]
C8  10uF  [0603]
C9  4.7uF  [TANT_A]
C10  0.01uF  [0402]
C11  22pF  [0603]
C12  22pF  [0603]
C13  0.1uF  [0603]
C14  0.1uF  [0603]
C15  0.1uF  [0603]
C16  0.1uF  [0603]
C17  0.1uF  [0603]
C18  0.1uF  [0603]
C19  0.1uF  [0603]
C20  27pF  [0603]
C21  27pF  [0603]
FB1  68 OHM @ 100MHz  [1206]
FB2  68 OHM @ 100MHz  [1206]
J5  USB_MINI_AB_MNE20-5G5P10  [CON_SMRT_USBMNE20_F]
L3  1K  @ 100MHZ  [0805]
R1  10  [0603]
R2  10  [0603]
R3  1K  [0603]
R4  12K  [0603]
R5  10K  [0402]
R6  10K  [0402]
R7  10K  [0402]
R8  2.2K  [0402]
R45  10K  [0402]
R46  4.7K  [0402]
R109  4.75K  [0402]
U2  TPS76933DBVT  [SOT_5_118x67_57]
U3  FT4232H  [LQFP_64_402x402_20]
U4  93LC46B-I/SN  [SOIC-8]
Y1  12MHz w/ 10pF  [XTAL_4_SM_130x102]

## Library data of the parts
J1 = HEADER_2x44_100: Mfr_Name: SAMTEC; Mfr_Part_number: SSQ-144-01-G-D; TI_SILKTEXT: CMOS
J3 = CON_SMVT_120POS_QSH_SAMTEC: Mfr_Name: Samtec; Mfr_Part_Number: QSH-060-01-L-D-A-RT1
SJP2 = JUMPER_SMD_L_0603: TI_Silktext: TRIGGER OPT
Z_SH-J6 = SHUNT-JUMPER-0603: Shunt: SHUNT 1-2
R17 R18 = R: Mfr_Name: Susumu Co Ltd; Mfr_Part_Number: RG1005P-49R9-B-T5; TOL: 5%
U5 = EP4SGX70F1152_2
C40 = CAPACITOR_NP_1: Mfr_Name: Murata; Mfr_Part_Number: GRM155R61A105KE15D; Tolerance: 10%; Voltage: 10V
C22-C34 C41 C45 C264 C291-C293 = CAP: Mfr_Name: Murata; Mfr_Part_Number: GRM155R61A104KA01D; Package: SMD; Type: Capacitor
C46 = CAP_0603: Mfr_Name: Murata; Mfr_Part_Number: GRM188R71C104KA01D
J7 = SMA-THVT_142-0701-201_REC: TI_Silktext: CMOS_CLK
L4 = BEAD_FERRITE_SM_1: Mfr_Name: TDK; Mfr_Part_Number: MPZ2012S331A
R15 R16 = RES_0603: Mfr_Name: Panasonic; Mfr_Part_Number: ERJ-3EKF1000V
R54 R56 R104 R105 = RES_0603: Mfr_Name: Panasonic; Mfr_Part_Number: ERJ-1GEF1000C
R76 = RES_0603: Mfr_Name: Panasonic; Mfr_Part_Number: ERJ-2RKF1000X
R89 R90 R99 = Res_0402_Zero: Mfr_Name: Panasonic; Mfr_Part_Number: ERJ-2GE0R00X
R91 R92 R163 = res_smd_0: Mfr_Name: Panasonic; Mfr_Part_Number: ERJ-2RKF1002X
R93 R94 = res_smd_0: Mfr_Name: Panasonic; Mfr_Part_Number: ERJ-2RKF2001X
U6 = SN65LVDS1DBVR: Mfr_Name: TI
Y2 = OSC: 100MHz, 25ppm, CL=15pF, 3.3V, Size=3X5 mm; Mfr_Name: Pletronics; Mfr_Part_Number: SM5545TEV-100.0M; Package: SMD; Terasic_Prt: M0923; Type: Crystal
C1 C5 C13-C19 C338-C342 = CAP0603: Mfr_Name: Murata; Mfr_Part_Number: GRM188R71C104KA01D; PART_NUMBER: ECJ-1VB1C104K; TOL: 10%; Voltage: 16V
C349 C350 = CAP_0402_0.1uF: Mfr_Name: Murata
D1-D9 = LED: Mfr_Name: Liteon; Mfr_Part_Number: LTST-C170KGKT; Package: SMD; Terasic_Prt: M0200
J18 = CON_THVT_MOLEX_22-23-2031: Mfr_Name: Molex; Mfr_Part_Number: 22-11-2032; TI_SILKTEXT: FAN_PWR
R67 R100-R102 = Res_0402_Zero: Mfr_Name: Panasonic
R68-R75 = RES0603: Mfr_Name: Panasonic; Mfr_Part_Number: ERJ-3EKF1650V
R77 R79 R109 = RESISTOR: Mfr_Name: Panasonic; Mfr_Part_Number: ERJ-2RKF4751X; Type: Resistor
R80-R83 R85-R87 R103 = RES: Mfr_Name: Panasonic; Mfr_Part_Number: ERJ-2RKF1001X
R84 R88 = RES: Mfr_Name: Panasonic; Mfr_Part_Number: ERJ-2RKF1001X_DNI; Note: DNI
R116 R154 = RES: Mfr_Name: Panasonic; Mfr_Part_Number: ERJ-3GEY0R00V; Type: Resistor
R155 = RES: Mfr_Name: Panasonic; Mfr_Part_Number: ERJ-3GEY0R00V_DNI; Note: DNI; Type: Resistor
SW1 = SW-DIP8: SMD DIP Switch 4 PoleS, Pitch = 1.27 mm, L6.6*W8*T2.5 mm; Mfr_Name: CK Components; Package: SMD; Terasic_Prt: M0759; Type: Switch
SW2 = SW_SMVT_SPST_4_KT11P3JM: Mfr_Name: ITT Industries; TI_SILKTEXT: CONF/SP1
SW3 = SW_SMVT_SPST_4_KT11P3JM: Mfr_Name: ITT Industries; TI_SILKTEXT: PUSHBUTTON1
SW4 = SW_SMVT_SPST_4_KT11P3JM: Mfr_Name: ITT Industries; TI_SILKTEXT: PUSHBUTTON2
SW5 = SW_SMVT_SPST_4_KT11P3JM: Mfr_Name: ITT Industries; TI_SILKTEXT: PUSHBUTTON3
SW6 = SW_SMVT_SPST_4_KT11P3JM: Mfr_Name: ITT Industries; TI_SILKTEXT: CPU_RESET
SW7 = SW_SLIDE-4P2T_1: Slide Switch; Mfr_Name: E-SWITCH; Mfr_Part_Number: EG4208A
TP22-TP27 = TP_THVT_060_RND-BLK: Mfr_Name: Components Corporation; Mfr_Part_Number: TP-105-01-00; TI_SILKTEXT: GND
U1 U14 = SN74LVC3G07DCU: Mfr_Name: Texas Instruments
Z_BOARD1 = BARE_BOARD: Mfr_Name: VIASYSTEMS; Mfr_Part_Number: TSW1400 REV E
Z_FANHEATSINK = HEATSINK: Mfr_Name: RADIAN HEATSINKS; Mfr_Part_Number: FB3L3
Z_STANDOFF1-Z_STANDOFF5 = STANDOFF: Mfr_Name: KEYSTONE; Mfr_Part_Number: 2204
Z_STANDOFF SCREW1-Z_STANDOFF SCREW5 = SCREW-STANDOFF: Mfr_Part_Number: PMSSS 440 0050 PH
D10 = LED: Mfr_Name: Panasonic; Mfr_Part_Number: LNJ306G5UUX; PART_NUMBER: Panasonic LNJ306G5UUX; TI_Silktext: J4
F2 = LITTELFUSE_0154007: Mfr_Part_Number: 0154002.DR_DNI; Note: DNI
J4 = CON_SMVT_180POS_QSH_SAMTEC: Mfr_Name: Samtec; Mfr_Part_Number: QSH-090-01-L-D-A-RT1
R65 = R_0: Mfr_Name: Panasonic; Mfr_Part_Number: ERJ-2RKF1001X; TOL: 1%
C35 = CAP: Mfr_Name: Murata; Mfr_Part_Number: GRM32ER60J107ME20L; TOL: 20%; VOLTAGE: 6.3V
C2 C6 C36 = CAP_NP_0: Mfr_Name: Kemet; Mfr_Part_Number: C0603C475K8PACTU; TOL: 10%; VOLTAGE: 10V
C37 = CAP: 2.2uF, +/-10%, 10V, X5R(0603); Mfr_Name: Yageo; Mfr_Part_Number: CC0603KRX5R6BB225; Package: SMD; Terasic_Prt: MCC-2000-YGO; Type: Capacitor
C38 = CAP: Mfr_Name: Murata; Mfr_Part_Number: GRM155R61A105KE15D; Tolerance: 10%; Voltage: 10V
C39 = CAP: Mfr_Name: Murata; Mfr_Part_Number: GRM155F51A474ZE01D
CN1 CN4 CN7 CN10 = CA: CAP - 4 ARRAY, 0.1UF, 25V, Y5V, -20/+80%; Mfr_Name: AVX; Mfr_Part_Number: W3A4YC104KAT2A; Package: SMD; Terasic_Prt: M0643; Type: Capacitor
J6 = SOCKET-SO-DIMM200: Mfr_Name: Tyco; Mfr_Part_Number: 1473005-4
R9 R10 = RES: Mfr_Name: Panasonic; Mfr_Part_Number: ERJ-2RKF1002X; Type: Resistor
RN8 RN9 RN12 RN13 RN18 RN19 RN24 = RA-8P4R: 56 ohm, +/-5%, 1/16W, 8P4R, Convex(0402*4); Mfr_Name: Yageo; Mfr_Part_Number: YC124-JR-0756R; Package: SMD; Terasic_Prt: M1241; Type: Resistor
C3 C8 = CAP_NP: Mfr_Name: Murata; Mfr_Part_Number: GRM188R60J106ME47D; TOL: 20%; VOLTAGE: 6.3V
C4 C7 = CAP_NP: Mfr_Name: Kemet; Mfr_Part_Number: C1206C107M9PACTU; TOL: 20%; VOLTAGE: 6.3V
C9 = CAP_POL-A: Mfr_Name: AVX; Mfr_Part_Number: TAJA475K006RNJ; TOL: 10%; Voltage: 6.3V
C10 = CAP0402: Mfr_Name: Murata; Mfr_Part_Number: GRM155R71E103KA01D; TOL: +/-10%; Voltage: 25V
C11 C12 = CAP_NP: Mfr_Name: Murata; Mfr_Part_Number: GRM1885C2A220JA01D_DNI; Note: DNI; PART_NUMBER: GRM1885C2A220JA01D; TOL: 5%; VOLTAGE: 100V
C20 C21 = CAP_NP: GROUP: NOT INSTALLED; Mfr_Name: Murata; Mfr_Part_Number: ERB1885C2E270JDX5D; PART_NUMBER: GRM1885C2A330JA01D; TOL: 5%; VOLTAGE: 100V
FB1 FB2 = FERRITE_BEAD: Mfr_Name: Panasonic; Mfr_Part_Number: EXC-ML32A680U; PART_NUMBER: Panasonic EXC-ML32A680U
J5 = USB_MINI_AB_MNE20-5G5P10: Mfr_Name: ACON; Mfr_Part_Number: MNE20-5G5P10; TI_SILKTEXT: 5V_USB
L3 = FERRITE_BEAD_0: CLASS: DISCRETE; Mfr_Name: Murata; Mfr_Part_Number: BLM21AG102SN1D
R1 R2 = R: Mfr_Name: PANASONIC; Mfr_Part_Number: ERJ-3GEYJ100V; TOL: 1%; Wattage: 1/10W
R3 = R: Mfr_Name: Panasonic; Mfr_Part_Number: ERJ-3EKF1001V
R4 = R: Mfr_Name: Panasonic; Mfr_Part_Number: ERJ-3EKF1202V; PART_NUMBER: ERJ-3EKF1202V; TOL: 1%
R5-R7 R45 = RESISTOR: Mfr_Name: Panasonic; Mfr_Part_Number: ERJ-2RKF1002X; Type: Resistor
R8 = RESISTOR: Mfr_Name: Panasonic; Mfr_Part_Number: ERJ-2RKF2201X; Type: Resistor
R46 = RESISTOR: Mfr_Name: Panasonic; Mfr_Part_Number: ERJ-2RKF4701X; Type: Resistor
U2 = TPS769XX-SOT23_0: Mfr_Name: Texas Instruments
U3 = FT4232H_2
U4 = EEPROM: 93LC46B-I/SN,Serial EEPROM, 64 x 16bit, 2.5V-5.5V; Mfr_Name: Microchip; Package: SMD; Terasic_Prt: M0252; Type: Memory
Y1 = CRYSTAL1-4_SM: Mfr_Name: Abracon; Mfr_Part_Number: ABM8G-12.000MHZ-B4Y-T

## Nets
0.9V: U5.AE25(VREFB2AN0) U5.AG14(VREFB4AN0) U5.AG20(VREFB3AN0) U5.AH19(VREFB3CN0) U5.AJ16(VREFB4CN0) ; also on sheet 16 18 20
0.9V_DDR: CN1.1 CN1.2 CN1.3 CN1.4 CN4.1 CN4.2 CN4.3 CN4.4 CN7.1 CN7.2 CN7.3 CN7.4 CN10.1 CN10.2 CN10.3 CN10.4 RN8.1 RN8.2 RN8.3 RN8.4 RN9.1 RN9.2 RN9.3 RN9.4 RN12.1 RN12.2 RN12.3 RN12.4 RN13.1 RN13.2 RN13.3 RN13.4 RN18.1 RN18.2 RN18.3 RN18.4 RN19.1 RN19.2 RN19.3 RN19.4 RN24.1 RN24.2 RN24.3 RN24.4 ; also on sheet 16
0.9V_VREF: C34.1 J6.1(VREF) ; also on sheet 16
1.8V: C22.1 C23.1 C24.1 C25.1 C26.1 C27.1 C28.1 C29.1 C30.1 C31.1 C32.1 C33.1 C35.1 C36.1 C37.1 C38.1 C39.1 J6.81(VDD) J6.82(VDD) J6.87(VDD) J6.88(VDD) J6.95(VDD) J6.96(VDD) J6.103(VDD) J6.104(VDD) J6.111(VDD) J6.112(VDD) J6.117(VDD) J6.118(VDD) J6.199(VDDSPD) R9.1 R10.1 R18.1 ; also on sheet 14 16 18 20
1.8V_USB: C3.1 C4.1 C13.1 C14.1 C15.1 U3.12(VCORE) U3.37(VCORE) U3.49(VREGOUT) U3.64(VCORE)
3.3V: C45.1 L4.1 R15.1 R68.1 R69.1 R70.1 R71.1 R72.1 R73.1 R74.1 R75.1 R80.1 R81.1 R82.1 R83.1 R84.1 R85.1 R86.1 R87.1 R88.1 Y2.1(EN) Y2.4(VCC) ; also on sheet 17 18
3.3V_CLKB: C40.1 C41.1 L4.2 U6.1(VCC)
3.3V_USB: C7.1 C9.1 C16.1 C17.1 C18.1 C19.1 FB1.1 FB2.1 R5.1 R6.1 R7.1 R109.1 U2.5(OUT) U3.20(VCCIO) U3.31(VCCIO) U3.42(VCCIO) U3.50(VREGIN) U3.56(VCCIO) U4.6(ORG) U4.8(VCC)
5V_IN: C349.1 C350.1 R77.1 R79.1 R154.2 R155.2 U1.8(VCC) U14.8(VCC) ; also on sheet 16 17 18
5V_USB: C8.1 L3.2 U2.1(IN)
6.0V_OUT: F2.1 ; also on sheet 17
GND: C1.2 C2.2 C3.2 C4.2 C5.2 C6.2 C7.2 C8.2 C9.2 C10.2 C11.2 C12.2 C13.2 C14.2 C15.2 C16.2 C17.2 C18.2 C19.2 C20.2 C21.2 C22.2 C23.2 C24.2 C25.2 C26.2 C27.2 C28.2 C29.2 C30.2 C31.2 C32.2 C33.2 C34.2 C35.2 C36.2 C37.2 C38.2 C39.2 C40.2 C41.2 C45.2 C338.2 C339.2 C340.2 C341.2 C342.2 C349.2 C350.2 CN1.5 CN1.6 CN1.7 CN1.8 CN4.5 CN4.6 CN4.7 CN4.8 CN7.5 CN7.6 CN7.7 CN7.8 CN10.5 CN10.6 CN10.7 CN10.8 D1.2(CATHODE) D10.2(CATHODE) J1.2 J1.4 J1.6 J1.8 J1.10 J1.12 J1.14 J1.16 J1.18 J1.20 J1.22 J1.24 J1.26 J1.28 J1.30 J1.32 J1.34 J1.36 J1.38 J1.40 J1.42 J1.44 J1.46 J1.48 J1.50 J1.52 J1.54 J1.56 J1.58 J1.60 J1.62 J1.64 J1.66 J1.68 J1.70 J1.72 J1.74 J1.76 J1.78 J1.80 J1.82 J1.84 J1.86 J1.88 J3.5 J3.6 J3.11 J3.12 J3.17 J3.18 J3.23 J3.24 J3.29 J3.30 J3.35 J3.36 J3.41 J3.42 J3.47 J3.48 J3.53 J3.54 J3.59 J3.60 J3.61 J3.62 J3.67 J3.68 J3.73 J3.74 J3.79 J3.80 J3.85 J3.86 J3.91 J3.92 J3.97 J3.98 J3.103 J3.104 J3.110 J3.116 J3.121(GND) J3.122(GND) J3.123(GND) J3.124(GND) J3.125(GND) J3.126(GND) J3.127(GND) J3.128(GND) J4.7 J4.8 J4.9 J4.10 J4.65 J4.66 J4.71 J4.72 J4.77 J4.78 J4.83 J4.84 J4.89 J4.90 J4.95 J4.96 J4.101 J4.102 J4.107 J4.108 J4.113 J4.114 J4.119 J4.120 J4.125 J4.126 J4.131 J4.132 J4.137 J4.138 J4.143 J4.144 J4.149 J4.150 J4.155 J4.156 J4.161 J4.162 J4.167 J4.168 J4.173 J4.174 J4.179 J4.180 J4.181(GND) J4.182(GND) J4.183(GND) J4.184(GND) J4.185(GND) J4.186(GND) J4.187(GND) J4.188(GND) J4.189(GND) J4.190(GND) J4.191(GND) J4.192(GND) J5.5(GND) J5.6(GND1) J5.7(GND2) J5.8(GND3) J5.9(GND4) J6.2(VSS) J6.3(VSS) J6.8(VSS) J6.9(VSS) J6.12(VSS) J6.15(VSS) J6.18(VSS) J6.21(VSS) J6.24(VSS) J6.27(VSS) J6.28(VSS) J6.33(VSS) J6.34(VSS) J6.39(VSS) J6.40(VSS) J6.41(VSS) J6.42(VSS) J6.47(VSS) J6.48(VSS) J6.53(VSS) J6.54(VSS) J6.59(VSS) J6.60(VSS) J6.65(VSS) J6.66(VSS) J6.71(VSS) J6.72(VSS) J6.77(VSS) J6.78(VSS) J6.121(VSS) J6.122(VSS) J6.127(VSS) J6.128(VSS) J6.132(VSS) J6.133(VSS) J6.138(VSS) J6.139(VSS) J6.144(VSS) J6.145(VSS) J6.149(VSS) J6.150(VSS) J6.155(VSS) J6.156(VSS) J6.161(VSS) J6.162(VSS) J6.165(VSS) J6.168(VSS) J6.171(VSS) J6.172(VSS) J6.177(VSS) J6.178(VSS) J6.183(VSS) J6.184(VSS) J6.187(VSS) J6.190(VSS) J6.193(VSS) J6.196(VSS) J6.198(SA0) J6.200(SA1) J7.2(GND) J7.3(GND) J7.4(GND) J7.5(GND) J18.1 R4.2 R16.2 R17.1 R45.2 R89.1 R90.1 R91.2 R92.2 R93.2 R94.2 R116.1 R163.2 SW1.1(A1) SW1.2(A2) SW1.3(A3) SW1.4(A4) SW2.1 SW2.2 SW3.1 SW3.2 SW4.1 SW4.2 SW5.1 SW5.2 SW6.1 SW6.2 SW7.3 SW7.6 SW7.9 SW7.12 TP22.1(TP) TP23.1(TP) TP24.1(TP) TP25.1(TP) TP26.1(TP) TP27.1(TP) U1.4(GND) U2.2(GND) U2.3(~{EN}) U3.1(GND) U3.5(GND) U3.10(AGND) U3.11(GND) U3.13(TEST) U3.15(GND) U3.25(GND) U3.35(GND) U3.47(GND) U3.51(GND) U4.5(GND) U4.7(NC) U5.AB25(VREFB2CN0) U5.AC9(VREFB5CN0) U5.AF8(VREFB5AN0) U5.AK1(RREF_R0) U5.D1(RREF_R1) U5.F16(VREFB7CN0) U5.G14(VREFB7AN0) U5.G19(VREFB8CN0) U5.H20(VREFB8AN0) U5.K9(VREFB6AN0) U5.M21(NC) U5.M22(NC) U5.M25(VREFB1AN0) U5.R9(VREFB6CN0) U5.R26(VREFB1CN0) U6.2(GND) U14.4(GND) Y1.2 Y1.4 Y2.2(GND) ; also on sheet 14 15 16 17 18 19 20 21
ADBUS0: U3.16(ADBUS0) ; also on sheet 15
ADBUS1: U3.17(ADBUS1) ; also on sheet 15
ADBUS2: U3.18(ADBUS2) ; also on sheet 15
ADBUS3: U3.19(ADBUS3) ; also on sheet 15
ADBUS4: U3.21(ADBUS4) ; also on sheet 14
ADBUS5: U3.22(ADBUS5) ; also on sheet 14
ADBUS6: U3.23(ADBUS6) ; also on sheet 14
ADBUS7: U3.24(ADBUS7) ; also on sheet 14
ADC_GPIO_0: J3.105 ; also on sheet 14
ADC_GPIO_1: J3.107 ; also on sheet 14
ADC_GPIO_2: J3.109 ; also on sheet 14
ADC_GPIO_3: SJP2.1(Pin1) ; also on sheet 14
ADC_GPIO_4: J3.113 ; also on sheet 14
ADC_GPIO_5: J3.115 ; also on sheet 14
ADC_GPIO_6: J3.117 ; also on sheet 14
ADC_GPIO_7: J3.119 ; also on sheet 14
ADC_TRIG: SJP2.3(Pin3) ; also on sheet 15
BDBUS0: U3.26(BDBUS0) ; also on sheet 15
BDBUS1: U3.27(BDBUS1) ; also on sheet 15
BDBUS2: U3.28(BDBUS2) ; also on sheet 15
BDBUS3: U3.29(BDBUS3) ; also on sheet 15
BDBUS4: U3.30(BDBUS4) ; also on sheet 14
BDBUS5: U3.32(BDBUS5) ; also on sheet 14
BDBUS6: U3.33(BDBUS6) ; also on sheet 14
BDBUS7: U3.34(BDBUS7) ; also on sheet 14
CDBUS0: U3.38(CDBUS0) ; also on sheet 15
CDBUS1: U3.39(CDBUS1) ; also on sheet 15
CDBUS2: U3.40(CDBUS2) ; also on sheet 15
CDBUS3: U3.41(CDBUS3) ; also on sheet 15
CDBUS4: U3.43(CDBUS4) ; also on sheet 14
CDBUS5: U3.44(CDBUS5) ; also on sheet 14
CDBUS6: U3.45(CDBUS6) ; also on sheet 14
CDBUS7: U3.46(CDBUS7) ; also on sheet 14
CLK_OSCN: R76.1 U5.AP20(CLK5N_DIFFOUT_B31N) U6.4(Y)
CLK_OSCP: R76.2 U5.AN20(CLK5P_DIFFOUT_B31P) U6.3(Z)
CMOS_CLK: C46.2 R15.2 R16.1 U5.B18(CLK14P_DIFFIO_RX_T17P_DIFFOUT_T33P)
CMOS_PORT0_0: J1.1 U5.B15(CLK12P_DIFFIO_RX_T16P_DIFFOUT_T32P)
CMOS_PORT0_1: J1.3 ; also on sheet 15
CMOS_PORT0_2: J1.5 ; also on sheet 15
CMOS_PORT0_3: J1.7 ; also on sheet 15
CMOS_PORT0_4: J1.9 ; also on sheet 15
CMOS_PORT0_5: J1.11 ; also on sheet 15
CMOS_PORT0_6: J1.13 ; also on sheet 15
CMOS_PORT0_7: J1.15 ; also on sheet 15
CMOS_PORT0_8: J1.17 ; also on sheet 15
CMOS_PORT0_9: J1.19 ; also on sheet 15
CMOS_PORT0_10: J1.21 ; also on sheet 15
CMOS_PORT0_11: J1.23 ; also on sheet 15
CMOS_PORT0_12: J1.25 ; also on sheet 15
CMOS_PORT0_13: J1.27 ; also on sheet 15
CMOS_PORT0_14: J1.29 ; also on sheet 15
CMOS_PORT0_15: J1.31 ; also on sheet 15
CMOS_PORT0_16: J1.33 ; also on sheet 15
CMOS_PORT0_17: J1.35 ; also on sheet 15
CMOS_PORT0_18: J1.37 ; also on sheet 15
CMOS_PORT0_19: J1.39 ; also on sheet 15
CMOS_PORT0_20: J1.41 ; also on sheet 15
CMOS_PORT0_21: J1.43 ; also on sheet 15
CMOS_PORT1_0: J1.45 U5.B20(CLK15P_DIFFOUT_T34P)
CMOS_PORT1_1: J1.47 ; also on sheet 14
CMOS_PORT1_2: J1.49 ; also on sheet 14
CMOS_PORT1_3: J1.51 ; also on sheet 14
CMOS_PORT1_4: J1.53 ; also on sheet 14
CMOS_PORT1_5: J1.55 ; also on sheet 14
CMOS_PORT1_6: J1.57 ; also on sheet 14
CMOS_PORT1_7: J1.59 ; also on sheet 14
CMOS_PORT1_8: J1.61 ; also on sheet 14
CMOS_PORT1_9: J1.63 ; also on sheet 14
CMOS_PORT1_10: J1.65 ; also on sheet 14
CMOS_PORT1_11: J1.67 ; also on sheet 14
CMOS_PORT1_12: J1.69 ; also on sheet 14
CMOS_PORT1_13: J1.71 ; also on sheet 14
CMOS_PORT1_14: J1.73 ; also on sheet 14
CMOS_PORT1_15: J1.75 ; also on sheet 14
CMOS_PORT1_16: J1.77 ; also on sheet 14
CMOS_PORT1_17: J1.79 ; also on sheet 14
CMOS_PORT1_18: J1.81 ; also on sheet 14
CMOS_PORT1_19: J1.83 ; also on sheet 14
CMOS_PORT1_20: J1.85 ; also on sheet 15
CMOS_PORT1_21: J1.87 ; also on sheet 15
CMOS_SP1: J4.26 ; also on sheet 14
CMOS_SP2: J4.28 ; also on sheet 14
CMOS_SP3: J4.38 ; also on sheet 14
CMOS_SP4: J4.40 ; also on sheet 14
CMOS_SP5: J4.46 ; also on sheet 14
CMOS_SP6: J4.50 ; also on sheet 14
CMOS_SP7: J4.52 ; also on sheet 14
CPU_RESET: R103.1 U5.A17(CLK13N_DIFFOUT_T31N)
DA0N: J4.165 U5.AB26(IO_2C_AB26/DQ10L/DIFFIO_TX_L19N/DIFFOUT_L38N)
DA0P: J4.163 U5.AC25(IO_2C_AC25/DQ10L/DIFFIO_TX_L19P/DIFFOUT_L38P)
DA1N: J4.159 U5.AA27(IO_2C_AA27/DQ8L/DIFFIO_TX_L16N/DIFFOUT_L32N)
DA1P: J4.157 U5.AA26(IO_2C_AA26/DQ8L/DIFFIO_TX_L16P/DIFFOUT_L32P)
DA2N: J4.153 U5.Y25(IO_2C_Y25/DIFFIO_TX_L20N/DIFFOUT_L40N)
DA2P: J4.151 U5.AA24(IO_2C_AA24/DIFFIO_TX_L20P/DIFFOUT_L40P)
DA3N: J4.147 U5.Y24(IO_2C_Y24/DQ9L/DIFFIO_TX_L18N/DIFFOUT_L36N)
DA3P: J4.145 U5.Y23(IO_2C_Y23/DQ9L/DIFFIO_TX_L18P/DIFFOUT_L36P)
DA4N: J4.141 U5.W23(IO_2C_W23/DQ9L/DIFFIO_TX_L17N/DIFFOUT_L34N)
DA4P: J4.139 U5.Y22(IO_2C_Y22/DQ9L/DIFFIO_TX_L17P/DIFFOUT_L34P)
DA5N: J4.135 U5.V25(IO_2C_V25/DIFFIO_TX_L15N/DIFFOUT_L30N)
DA5P: J4.133 U5.W24(IO_2C_W24/DIFFIO_TX_L15P/DIFFOUT_L30P)
DA6N: J4.129 U5.U25(IO_1C_U25/DQ6L/DIFFIO_TX_L12N/DIFFOUT_L23N/DATA4)
DA6P: J4.127 U5.T24(IO_1C_T24/DQ6L/DIFFIO_TX_L12P/DIFFOUT_L23P/DATA5)
DA7N: J4.123 U5.R24(IO_1C_R24/DQ7L/DIFFIO_TX_L13N/DIFFOUT_L25N/INIT_DONE)
DA7P: J4.121 U5.R23(IO_1C_R23/DQ7L/DIFFIO_TX_L13P/DIFFOUT_L25P/CRC_ERROR)
DA8N: J4.111 U5.J27(IO_1A_J27/DQ4L/DIFFIO_TX_L7N/DIFFOUT_L13N)
DA8P: J4.109 U5.H26(IO_1A_H26/DQ4L/DIFFIO_TX_L7P/DIFFOUT_L13P)
DA9N: J4.105 U5.P24(IO_1A_P24/DQ3L/DIFFIO_TX_L5N/DIFFOUT_L9N)
DA9P: J4.103 U5.P23(IO_1A_P23/DQ3L/DIFFIO_TX_L5P/DIFFOUT_L9P)
DA10N: J4.99 U5.N26(IO_1C_N26/DIFFIO_TX_L9N/DIFFOUT_L17N)
DA10P: J4.97 U5.N25(IO_1C_N25/DIFFIO_TX_L9P/DIFFOUT_L17P)
DA11N: J4.93 U5.M24(IO_1A_M24/DIFFIO_TX_L8N/DIFFOUT_L15N)
DA11P: J4.91 U5.N23(IO_1A_N23/DIFFIO_TX_L8P/DIFFOUT_L15P)
DA12N: J4.87 U5.N27(IO_1C_N27/DQ5L/DIFFIO_TX_L10N/DIFFOUT_L19N/CLKUSR)
DA12P: J4.85 U5.M26(IO_1C_M26/DQ5L/DIFFIO_TX_L10P/DIFFOUT_L19P)
DA13N: J4.81 U5.K27(IO_1A_K27/DQ2L/DIFFIO_TX_L4N/DIFFOUT_L7N)
DA13P: J4.79 U5.K26(IO_1A_K26/DQ2L/DIFFIO_TX_L4P/DIFFOUT_L7P)
DA14N: J4.75 U5.L23(IO_1A_L23/DQ1L/DIFFIO_TX_L2N/DIFFOUT_L3N)
DA14P: J4.73 U5.M23(IO_1A_M23/DQ1L/DIFFIO_TX_L2P/DIFFOUT_L3P)
DA15N: J4.69 U5.K24(IO_1A_K24/DIFFIO_TX_L1N/DIFFOUT_L1N)
DA15P: J4.67 U5.L24(IO_1A_L24/DIFFIO_TX_L1P/DIFFOUT_L1P)
DAC_GPIO_0: J4.45 ; also on sheet 14
DAC_GPIO_1: J4.47 ; also on sheet 14
DAC_GPIO_2: J4.49 ; also on sheet 14
DAC_GPIO_3: J4.51 ; also on sheet 14
DAC_GPIO_4: J4.53 ; also on sheet 14
DAC_GPIO_5: J4.55 ; also on sheet 14
DAC_GPIO_6: J4.57 ; also on sheet 14
DAC_GPIO_7: J4.59 ; also on sheet 14
DACLKN: J4.117 U5.M29(IO_1C_M29/PLL_L2_CLKOUT0N/DIFFIO_TX_L14N/DIFFOUT_L27N)
DACLKP: J4.115 U5.M28(IO_1C_M28/PLL_L2_FB_CLKOUT0P/DIFFIO_TX_L14P/DIFFOUT_L27P)
DB0N: J4.166 ; also on sheet 12
DB0P: J4.164 ; also on sheet 12
DB1N: J4.160 ; also on sheet 12
DB1P: J4.158 ; also on sheet 12
DB2N: J4.154 ; also on sheet 12
DB2P: J4.152 ; also on sheet 12
DB3N: J4.148 ; also on sheet 12
DB3P: J4.146 ; also on sheet 12
DB4N: J4.142 ; also on sheet 12
DB4P: J4.140 ; also on sheet 12
DB5N: J4.136 ; also on sheet 12
DB5P: J4.134 ; also on sheet 12
DB6N: J4.130 ; also on sheet 12
DB6P: J4.128 ; also on sheet 12
DB7N: J4.124 ; also on sheet 12
DB7P: J4.122 ; also on sheet 12
DB8N: J4.112 ; also on sheet 12
DB8P: J4.110 ; also on sheet 12
DB9N: J4.106 ; also on sheet 12
DB9P: J4.104 ; also on sheet 12
DB10N: J4.100 ; also on sheet 12
DB10P: J4.98 ; also on sheet 12
DB11N: J4.94 ; also on sheet 12
DB11P: J4.92 ; also on sheet 12
DB12N: J4.88 ; also on sheet 12
DB12P: J4.86 ; also on sheet 12
DB13N: J4.82 ; also on sheet 12
DB13P: J4.80 ; also on sheet 12
DB14N: J4.76 ; also on sheet 13
DB14P: J4.74 ; also on sheet 13
DB15N: J4.70 ; also on sheet 13
DB15P: J4.68 ; also on sheet 13
DBCLKN: J4.39 ; also on sheet 13
DBCLKP: J4.37 ; also on sheet 13
DCLK_M: J3.56 R54.1 U5.AA6(CLK8N)
DCLK_P: J3.58 R54.2 U5.AA7(CLK8P)
DDBUS4: U3.55(DDBUS4) ; also on sheet 15
DDBUS5: U3.57(DDBUS5) ; also on sheet 15
DDR2_A0: J6.102(A0) RN12.6 U5.AE24(IO_2A_AE24/DQ14L/DIFFIO_TX_L26N/DIFFOUT_L52N)
DDR2_A1: J6.101(A1) RN13.7 U5.AF23(IO_2A_AF23/DQ14L/DIFFIO_TX_L26P/DIFFOUT_L52P)
DDR2_A2: J6.100(A2) RN13.8 U5.AF25(IO_2A_AF25/DQ11L/DIFFIO_TX_L22N/DIFFOUT_L44N)
DDR2_A3: J6.99(A3) RN13.5 U5.AF26(IO_2A_AF26/DQ12L/DIFFIO_TX_L24P/DIFFOUT_L48P)
DDR2_A4: J6.98(A4) RN13.6 U5.AF27(IO_2A_AF27/DQ12L/DIFFIO_TX_L24N/DIFFOUT_L48N)
DDR2_A5: J6.97(A5) RN18.7 U5.AG23(IO_2A_AG23/DQ12L/DIFFIO_TX_L23P/DIFFOUT_L46P)
DDR2_A6: J6.94(A6) RN18.8 U5.AG24(IO_2A_AG24/DQ11L/DIFFIO_TX_L22P/DIFFOUT_L44P)
DDR2_A7: J6.92(A7) RN18.6 U5.AG26(IO_2A_AG26/DQ13L/DIFFIO_TX_L25P/DIFFOUT_L50P)
DDR2_A8: J6.93(A8) RN18.5 U5.AG27(IO_2A_AG27/DQ13L/DIFFIO_TX_L25N/DIFFOUT_L50N)
DDR2_A9: J6.91(A9) RN19.7 U5.AH28(IO_2A_AH28/DQS12L/DIFFIO_RX_L24P/DIFFOUT_L47P)
DDR2_A10: J6.105(A10/AP) RN12.5 U5.AJ26(IO_2A_AJ26/DQ11L/DIFFIO_RX_L22P/DIFFOUT_L43P)
DDR2_A11: J6.90(A11) RN19.8 U5.AJ28(IO_2A_AJ28/DQ13L/DIFFIO_RX_L25P/DIFFOUT_L49P)
DDR2_A12: J6.89(A12) RN19.5 U5.AJ29(IO_2A_AJ29/DQ13L/DIFFIO_RX_L25N/DIFFOUT_L49N)
DDR2_A13: J6.116(A13) RN8.8 U5.AK27(IO_2A_AK27/DQ11L/DIFFIO_RX_L22N/DIFFOUT_L43N)
DDR2_A14: J6.86(A14) RN19.6 U5.AL29(IO_2A_AL29/DQSN14L/DIFFIO_RX_L27N/DIFFOUT_L53N)
DDR2_A15: J6.84(A15) RN24.7 U5.AM28(IO_2A_AM28/DQS14L/DIFFIO_RX_L27P/DIFFOUT_L53P)
DDR2_BA0: J6.107(BA0) RN12.7 ; also on sheet 11
DDR2_BA1: J6.106(BA1) RN12.8 ; also on sheet 11
DDR2_BA2: J6.85(BA2) RN24.8 ; also on sheet 11
DDR2_CAS_n: J6.113(~{CAS}) RN9.7 ; also on sheet 11
DDR2_CKE0: J6.79(CKE0) RN24.6 ; also on sheet 11
DDR2_CKE1: J6.80(CKE1) RN24.5 ; also on sheet 10
DDR2_CLK_n0: J6.32(~{CK}0) ; also on sheet 11
DDR2_CLK_n1: J6.166(~{CK}1) ; also on sheet 11
DDR2_CLK_p0: J6.30(CK0) ; also on sheet 11
DDR2_CLK_p1: J6.164(CK1) ; also on sheet 11
DDR2_CS_n0: J6.110(~{S}0) RN9.8 ; also on sheet 11
DDR2_CS_n1: J6.115(~{S}1) RN8.7 ; also on sheet 10
DDR2_DM0: J6.10(DM0) ; also on sheet 11
DDR2_DM1: J6.26(DM1) ; also on sheet 11
DDR2_DM2: J6.52(DM2) ; also on sheet 10
DDR2_DM3: J6.67(DM3) ; also on sheet 11
DDR2_DM4: J6.130(DM4) ; also on sheet 10
DDR2_DM5: J6.147(DM5) ; also on sheet 10
DDR2_DM6: J6.170(DM6) ; also on sheet 11
DDR2_DM7: J6.185(DM7) ; also on sheet 10
DDR2_DQ0: J6.5(DQ0) ; also on sheet 11
DDR2_DQ1: J6.7(DQ1) ; also on sheet 11
DDR2_DQ2: J6.17(DQ2) ; also on sheet 11
DDR2_DQ3: J6.19(DQ3) ; also on sheet 11
DDR2_DQ4: J6.4(DQ4) ; also on sheet 11
DDR2_DQ5: J6.6(DQ5) ; also on sheet 11
DDR2_DQ6: J6.14(DQ6) ; also on sheet 11
DDR2_DQ7: J6.16(DQ7) ; also on sheet 11
DDR2_DQ8: J6.23(DQ8) ; also on sheet 11
DDR2_DQ9: J6.25(DQ9) ; also on sheet 11
DDR2_DQ10: J6.35(DQ10) ; also on sheet 11
DDR2_DQ11: J6.37(DQ11) ; also on sheet 11
DDR2_DQ12: J6.20(DQ12) ; also on sheet 11
DDR2_DQ13: J6.22(DQ13) ; also on sheet 11
DDR2_DQ14: J6.36(DQ14) ; also on sheet 11
DDR2_DQ15: J6.38(DQ15) ; also on sheet 11
DDR2_DQ16: J6.43(DQ16) ; also on sheet 10
DDR2_DQ17: J6.45(DQ17) ; also on sheet 10
DDR2_DQ18: J6.55(DQ18) ; also on sheet 10
DDR2_DQ19: J6.57(DQ19) ; also on sheet 10
DDR2_DQ20: J6.44(DQ20) ; also on sheet 10
DDR2_DQ21: J6.46(DQ21) ; also on sheet 10
DDR2_DQ22: J6.56(DQ22) ; also on sheet 10
DDR2_DQ23: J6.58(DQ23) ; also on sheet 10
DDR2_DQ24: J6.61(DQ24) ; also on sheet 11
DDR2_DQ25: J6.63(DQ25) ; also on sheet 11
DDR2_DQ26: J6.73(DQ26) ; also on sheet 11
DDR2_DQ27: J6.75(DQ27) ; also on sheet 11
DDR2_DQ28: J6.62(DQ28) ; also on sheet 11
DDR2_DQ29: J6.64(DQ29) ; also on sheet 11
DDR2_DQ30: J6.74(DQ30) ; also on sheet 11
DDR2_DQ31: J6.76(DQ31) ; also on sheet 11
DDR2_DQ32: J6.123(DQ32) ; also on sheet 10
DDR2_DQ33: J6.125(DQ33) ; also on sheet 10
DDR2_DQ34: J6.135(DQ34) ; also on sheet 10
DDR2_DQ35: J6.137(DQ35) ; also on sheet 10
DDR2_DQ36: J6.124(DQ36) ; also on sheet 10
DDR2_DQ37: J6.126(DQ37) ; also on sheet 10
DDR2_DQ38: J6.134(DQ38) ; also on sheet 10
DDR2_DQ39: J6.136(DQ39) ; also on sheet 10
DDR2_DQ40: J6.141(DQ40) ; also on sheet 10
DDR2_DQ41: J6.143(DQ41) ; also on sheet 10
DDR2_DQ42: J6.151(DQ42) ; also on sheet 10
DDR2_DQ43: J6.153(DQ43) ; also on sheet 10
DDR2_DQ44: J6.140(DQ44) ; also on sheet 10
DDR2_DQ45: J6.142(DQ45) ; also on sheet 10
DDR2_DQ46: J6.152(DQ46) ; also on sheet 10
DDR2_DQ47: J6.154(DQ47) ; also on sheet 10
DDR2_DQ48: J6.157(DQ48) ; also on sheet 11
DDR2_DQ49: J6.159(DQ49) ; also on sheet 11
DDR2_DQ50: J6.173(DQ50) ; also on sheet 11
DDR2_DQ51: J6.175(DQ51) ; also on sheet 11
DDR2_DQ52: J6.158(DQ52) ; also on sheet 11
DDR2_DQ53: J6.160(DQ53) ; also on sheet 11
DDR2_DQ54: J6.174(DQ54) ; also on sheet 11
DDR2_DQ55: J6.176(DQ55) ; also on sheet 11
DDR2_DQ56: J6.179(DQ56) ; also on sheet 10
DDR2_DQ57: J6.181(DQ57) ; also on sheet 10
DDR2_DQ58: J6.189(DQ58) ; also on sheet 10
DDR2_DQ59: J6.191(DQ59) ; also on sheet 10
DDR2_DQ60: J6.180(DQ60) ; also on sheet 10
DDR2_DQ61: J6.182(DQ61) ; also on sheet 10
DDR2_DQ62: J6.192(DQ62) ; also on sheet 10
DDR2_DQ63: J6.194(DQ63) ; also on sheet 10
DDR2_DQS0: J6.13(DQS0) ; also on sheet 11
DDR2_DQS1: J6.31(DQS1) ; also on sheet 11
DDR2_DQS2: J6.51(DQS2) ; also on sheet 10
DDR2_DQS3: J6.70(DQS3) ; also on sheet 11
DDR2_DQS4: J6.131(DQS4) ; also on sheet 10
DDR2_DQS5: J6.148(DQS5) ; also on sheet 10
DDR2_DQS6: J6.169(DQS6) ; also on sheet 11
DDR2_DQS7: J6.188(DQS7) ; also on sheet 10
DDR2_DQSn0: J6.11(~{DQS}0) ; also on sheet 11
DDR2_DQSn1: J6.29(~{DQS}1) ; also on sheet 11
DDR2_DQSn2: J6.49(~{DQS}2) ; also on sheet 10
DDR2_DQSn3: J6.68(~{DQS}3) ; also on sheet 11
DDR2_DQSn4: J6.129(~{DQS}4) ; also on sheet 10
DDR2_DQSn5: J6.146(~{DQS}5) ; also on sheet 10
DDR2_DQSn6: J6.167(~{DQS}6) ; also on sheet 11
DDR2_DQSn7: J6.186(~{DQS}7) ; also on sheet 10
DDR2_ODT0: J6.114(ODT0) RN8.6 ; also on sheet 11
DDR2_ODT1: J6.119(ODT1) RN8.5 ; also on sheet 10
DDR2_RAS_n: J6.108(~{RAS}) RN9.6 ; also on sheet 11
DDR2_SCL: J6.197(SCL) R10.2
DDR2_SDA: J6.195(SDA) R9.2
DDR2_WE_n: J6.109(~{WE}) RN9.5 ; also on sheet 11
DM: C12.1 R1.2 U3.7(DM)
DP: C11.1 R2.2 U3.8(DP)
DS3N: J4.22 ; also on sheet 13
DS3P: J4.20 ; also on sheet 13
DS5N: J4.34 ; also on sheet 13
DS5P: J4.32 ; also on sheet 13
EEDATA: R8.1 U3.61(EEDATA) U4.3(DI)
EN1: U14.7(1Y) ; also on sheet 16 17
EN2: U1.7(1Y) ; also on sheet 16
EN3: U1.5(2Y) ; also on sheet 16
EN4: U1.2(3Y) ; also on sheet 16
EN5: U14.5(2Y) ; also on sheet 17
EN6: U14.2(3Y) ; also on sheet 18
FCLK_M: J3.64 U5.AC6(CLK9N_DIFFIO_RX_R14N_DIFFOUT_R28N)
FCLK_P: J3.66 U5.AB6(CLK9P_DIFFIO_RX_R14P_DIFFOUT_R28P)
FPGA_CLK2_N: C293.2 J4.33
FPGA_CLK2_P: C292.2 J4.31
FPGA_CLKN: C264.2 J4.118
FPGA_CLKP: C291.2 J4.116
FPGA_CONF_DONE: R67.2 ; also on sheet 21
FPGACLK2N: C293.1 R105.2 U5.N6(CLK10N)
FPGACLK2P: C292.1 R105.1 U5.N7(CLK10P)
FPGACLKN: C264.1 R104.1 U5.N29(CLK1N)
FPGACLKP: C291.1 R104.2 U5.N28(CLK1P)
FTDI_BLAST_TDI: U3.52(DDBUS1) ; also on sheet 21
FTDI_BLAST_TDO: U3.53(DDBUS2) ; also on sheet 21
FTDI_NCE: U3.58(DDBUS6) ; also on sheet 15
FTDI_nCONFIG: R109.2 U3.59(DDBUS7) ; also on sheet 15
FTDI_TCK: U3.48(DDBUS0) ; also on sheet 21
FTDI_TMS: U3.54(DDBUS3) ; also on sheet 21
Input0_M: J3.2 U5.AE29(IO_2C_AE29/DQ10L/DIFFIO_RX_L19N/DIFFOUT_L37N)
Input0_P: J3.4 U5.AF28(IO_2C_AF28/DQ10L/DIFFIO_RX_L19P/DIFFOUT_L37P)
Input1_M: J3.8 U5.AD29(IO_2C_AD29/DQSN10L/DIFFIO_RX_L20N/DIFFOUT_L39N)
Input1_P: J3.10 U5.AE28(IO_2C_AE28/DQS10L/DIFFIO_RX_L20P/DIFFOUT_L39P)
Input2_M: J3.14 ; also on sheet 12
Input2_P: J3.16 ; also on sheet 12
Input3_M: J3.20 ; also on sheet 12
Input3_P: J3.22 ; also on sheet 12
Input4_M: J3.26 ; also on sheet 12
Input4_P: J3.28 ; also on sheet 12
Input5_M: J3.32 ; also on sheet 12
Input5_P: J3.34 ; also on sheet 12
Input6_M: J3.38 ; also on sheet 12
Input6_P: J3.40 ; also on sheet 12
Input7_M: J3.44 ; also on sheet 12
Input7_P: J3.46 ; also on sheet 12
Input8_M: J3.50 ; also on sheet 12
Input8_P: J3.52 ; also on sheet 12
Input9_M: J3.1 U5.AE27(IO_2C_AE27/DQSN8L/DIFFIO_RX_L17N/DIFFOUT_L33N)
Input9_P: J3.3 U5.AD26(IO_2C_AD26/DQS8L/DIFFIO_RX_L17P/DIFFOUT_L33P)
Input10_M: J3.7 U5.AD27(IO_2C_AD27/DQSN9L/DIFFIO_RX_L18N/DIFFOUT_L35N)
Input10_P: J3.9 U5.AC26(IO_2C_AC26/DQS9L/DIFFIO_RX_L18P/DIFFOUT_L35P)
Input11_M: J3.13 U5.AC28(IO_2C_AC28/DQ8L/DIFFIO_RX_L16N/DIFFOUT_L31N)
Input11_P: J3.15 U5.AB27(IO_2C_AB27/DQ8L/DIFFIO_RX_L16P/DIFFOUT_L31P)
Input12_M: J3.19 ; also on sheet 13
Input12_P: J3.21 ; also on sheet 13
Input13_M: J3.25 ; also on sheet 13
Input13_P: J3.27 ; also on sheet 13
Input14_M: J3.31 ; also on sheet 13
Input14_P: J3.33 ; also on sheet 13
Input15_M: J3.37 U5.M5(CLK11N_DIFFIO_RX_R15N_DIFFOUT_R29N)
Input15_P: J3.39 U5.M6(CLK11P_DIFFIO_RX_R15P_DIFFOUT_R29P)
Input16_M: J3.43 ; also on sheet 13
Input16_P: J3.45 ; also on sheet 13
Input17_M: J3.49 ; also on sheet 13
Input17_P: J3.51 ; also on sheet 13
Input18_M: J3.55 R56.2 U5.AA29(CLK3N)
Input18_P: J3.57 R56.1 U5.AA28(CLK3P)
Input19_M: J3.70 ; also on sheet 12
Input19_P: J3.72 ; also on sheet 12
Input20_M: J3.76 ; also on sheet 12
Input20_P: J3.78 ; also on sheet 12
Input21_M: J3.82 ; also on sheet 12
Input21_P: J3.84 ; also on sheet 12
Input22_M: J3.88 ; also on sheet 12
Input22_P: J3.90 ; also on sheet 12
Input23_M: J3.94 ; also on sheet 12
Input23_P: J3.96 ; also on sheet 12
Input24_M: J3.100 ; also on sheet 12
Input24_P: J3.102 ; also on sheet 12
Input25_M: J3.106 ; also on sheet 13
Input25_P: J3.108 ; also on sheet 13
Input26_M: J3.112 ; also on sheet 13
Input26_P: J3.114 ; also on sheet 13
Input27_M: J3.118 U5.M30(IO_1C_M30/DQ7L/DIFFIO_RX_L13N/DIFFOUT_L26N/DEV_OE)
Input27_P: J3.120 U5.L29(IO_1C_L29/DQ7L/DIFFIO_RX_L13P/DIFFOUT_L26P/DEV_CLRN)
Input28_M: J3.63 U5.K30(IO_1C_K30/DQSN6L/DIFFIO_RX_L11N/DIFFOUT_L22N/DATA2)
Input28_P: J3.65 U5.L30(IO_1C_L30/DQS6L/DIFFIO_RX_L11P/DIFFOUT_L22P/DATA3)
Input29_M: J3.69 ; also on sheet 13
Input29_P: J3.71 ; also on sheet 13
Input30_M: J3.75 ; also on sheet 13
Input30_P: J3.77 ; also on sheet 13
Input31_M: J3.81 ; also on sheet 13
Input31_P: J3.83 ; also on sheet 13
Input32_M: J3.87 ; also on sheet 13
Input32_P: J3.89 ; also on sheet 13
Input33_M: J3.93 ; also on sheet 13
Input33_P: J3.95 ; also on sheet 13
Input34_M: J3.99 ; also on sheet 13
Input34_P: J3.101 ; also on sheet 13
ISTROBE_N: J4.178 U5.J25(IO_1A_J25/DQ3L/DIFFIO_TX_L6N/DIFFOUT_L11N)
ISTROBE_P: J4.176 U5.H24(IO_1A_H24/DQ3L/DIFFIO_TX_L6P/DIFFOUT_L11P)
nCS: R99.1 ; also on sheet 21
OSTROBE_N: J4.171 ; also on sheet 13
OSTROBE_P: J4.169 ; also on sheet 13
PARITY_N: J4.172 ; also on sheet 21
PARITY_P: J4.170 ; also on sheet 21
PRESENT: J4.21 ; also on sheet 14
PUSHBUTTON1: R100.1 ; also on sheet 15
PUSHBUTTON2: R101.1 ; also on sheet 15
PUSHBUTTON3: R102.1 ; also on sheet 15
SYNCA_N: J4.177 U5.J26(IO_1A_J26/DQ1L/DIFFIO_TX_L3N/DIFFOUT_L5N)
SYNCA_P: J4.175 U5.K25(IO_1A_K25/DQ1L/DIFFIO_TX_L3P/DIFFOUT_L5P)
TXEN: J4.27 ; also on sheet 14
USB_EECLK: R6.2 U3.62(EECLK) U4.2(CLK)
USB_EECS: R5.2 U3.63(EECS) U4.1(CS)
USB_REF: R4.1 U3.6(REF)
USB_RST: R3.1 U3.14(RESET)
USB_VBUS: J5.1(VBUS) L3.1 R46.1
USER_DIP0: R80.2 SW1.8(B1) ; also on sheet 15
USER_DIP1: R81.2 SW1.7(B2) ; also on sheet 15
USER_DIP2: R82.2 SW1.6(B3) ; also on sheet 15
USER_DIP3: R83.2 SW1.5(B4) ; also on sheet 15
USER_LED0: D2.2(CATHODE) ; also on sheet 15
USER_LED1: D3.2(CATHODE) ; also on sheet 15
USER_LED2: D4.2(CATHODE) ; also on sheet 15
USER_LED3: D5.2(CATHODE) ; also on sheet 15
USER_LED4: D6.2(CATHODE) ; also on sheet 15
USER_LED5: D7.2(CATHODE) ; also on sheet 15
USER_LED6: D8.2(CATHODE) ; also on sheet 15
USER_LED7: D9.2(CATHODE) ; also on sheet 15
N24747082: R7.2 R8.2 U4.4(DO)
N25673570: C1.1 C2.1 FB1.2 U3.9(VPLL)
N25674940: C5.1 C6.1 FB2.2 U3.4(VPHY)
N27224376: J5.3(D+) R2.1
N27224380: J5.2(D-) R1.1
N27319544: C20.1 U3.2(OSCI) Y1.1
N27322325: C21.1 U3.3(OSCO) Y1.3
N28576821: J3.111 SJP2.2(Pin2)
N28621539: R3.2 R45.1 R46.2
N29450409: C46.1 J7.1(CENTER)
N32875249: R17.2 U5.AK29(RDN2A/DIFFIO_RX_L28N/DIFFOUT_L55N)
N32875251: R18.2 U5.AL28(RUP2A/DIFFIO_RX_L28P/DIFFOUT_L55P)
N38382982: C10.1 U2.4(NC/FB)
N44148054: R90.2 U5.B3(TEMPDIODEP)
N44148055: R89.2 U5.A3(TEMPDIODEN)
N44200403: R91.1 U5.AF1(GXB_RX_R1N) U5.AF2(GXB_RX_R1P) U5.AF33(GXB_RX_L1P) U5.AF34(GXB_RX_L1N) U5.AH1(GXB_RX_R0N) U5.AH2(GXB_RX_R0P) U5.AH33(GXB_RX_L0P) U5.AH34(GXB_RX_L0N) U5.F1(GXB_RX_R7N) U5.F2(GXB_RX_R7P) U5.F33(GXB_RX_L7P) U5.F34(GXB_RX_L7N) U5.H1(GXB_RX_R6N) U5.H2(GXB_RX_R6P) U5.H33(GXB_RX_L6P) U5.H34(GXB_RX_L6N) U5.P1(GXB_RX_R5N) U5.P2(GXB_RX_R5P) U5.P33(GXB_RX_L5P) U5.P34(GXB_RX_L5N) U5.T1(GXB_RX_R4N) U5.T2(GXB_RX_R4P) U5.T33(GXB_RX_L4P) U5.T34(GXB_RX_L4N) U5.V1(GXB_RX_R3N) U5.V2(GXB_RX_R3P) U5.V33(GXB_RX_L3P) U5.V34(GXB_RX_L3N) U5.Y1(GXB_RX_R2N) U5.Y2(GXB_RX_R2P) U5.Y33(GXB_RX_L2P) U5.Y34(GXB_RX_L2N)
N44225882: R92.1 U5.AB1(REFCLK_R1N,_GXB_CMURX_R1N) U5.AB2(REFCLK_R1P,_GXB_CMURX_R1P) U5.AD1(REFCLK_R0N,_GXB_CMURX_R0N) U5.AD2(REFCLK_R0P,_GXB_CMURX_R0P) U5.K1(REFCLK_R3N,_GXB_CMURX_R3N) U5.K2(REFCLK_R3P,_GXB_CMURX_R3P) U5.M1(REFCLK_R2N,_GXB_CMURX_R2N) U5.M2(REFCLK_R2P,_GXB_CMURX_R2P)
N44253255: R93.1 U5.D34(RREF_L1)
N44254573: R94.1 U5.AK34(RREF_L0)
N45611700: D7.1(ANODE) R72.2
N45611745: C339.1 R85.2 R100.2 SW3.3 SW3.4
N45611776: C341.1 R87.2 R102.2 SW5.3 SW5.4
N45611858: C342.1 R88.2 R103.2 SW6.3 SW6.4
N45611860: D3.1(ANODE) R69.2
N45611894: C340.1 R86.2 R101.2 SW4.3 SW4.4
N45612012: R79.2 SW7.2 U1.1(1A) U1.3(2A) U1.6(3A)
N45612026: J18.2 SW7.8 SW7.11
N45612034: R77.2 SW7.5 U14.1(1A) U14.3(2A) U14.6(3A)
N45612058: C338.1 R84.2 R99.2 SW2.3 SW2.4
N45612265: D4.1(ANODE) R70.2
N45612267: D5.1(ANODE) R71.2
N45612353: D8.1(ANODE) R74.2
N45612355: D9.1(ANODE) R75.2
N45612432: D2.1(ANODE) R68.2
N45612555: D6.1(ANODE) R73.2
N45612557: D1.1(ANODE) R67.1
N45639686: F2.2 J4.1 J4.2 J4.3 J4.4 R65.2
N45639690: D10.1(ANODE) R65.1
N45835930: U6.5(D) Y2.3(OUT)
N45842022: R154.1 SW7.7 SW7.10
N46037928: R163.1 U5.AB33(REFCLK_L1P,_GXB_CMURX_L1P) U5.AB34(REFCLK_L1N,_GXB_CMURX_L1N) U5.AD33(REFCLK_L0P,_GXB_CMURX_L0P) U5.AD34(REFCLK_L0N,_GXB_CMURX_L0N) U5.K33(REFCLK_L3P,_GXB_CMURX_L3P) U5.K34(REFCLK_L3N,_GXB_CMURX_L3N) U5.M33(REFCLK_L2P,_GXB_CMURX_L2P) U5.M34(REFCLK_L2N,_GXB_CMURX_L2N)
N46194438: J18.3 R116.2 R155.1

Not connected (* = marked no-connect by the designer): J4 5 6 11 12 13 14 15 16 17 18 19 23 24 25 29 30 35 36 41 42 43 44 48 54 56 58 60 61 62 63 64; J5 4(ID)*; J6 50(NC0)* 69(NC1)* 83(NC2)* 120(NC3)* 163(TEST)*; SW7 1* 4*; U3 36(SUSPEND)* 60(PWREN)*; U5 A2(NC)* A15(CLK12N_DIFFIO_RX_T16N_DIFFOUT_T32N)* A18(CLK14N_DIFFIO_RX_T17N_DIFFOUT_T33N)* A20(CLK15N_DIFFOUT_T34N)* A32(NC)* AA3(GXB_CMUTX_R1N)* AA4(GXB_CMUTX_R1P)* AA23(IO_2A_AA23/DQ14L/DIFFIO_TX_L27N/DIFFOUT_L54N)* AA31(GXB_CMUTX_L1P)* AA32(GXB_CMUTX_L1N)* AB23(IO_2A_AB23/DQ14L/DIFFIO_TX_L27P/DIFFOUT_L54P)* AB29(CLK2N_DIFFIO_RX_L15N_DIFFOUT_L29N)* AC3(GXB_CMUTX_R0N)* AC4(GXB_CMUTX_R0P)* AC13(NC)* AC14(NC)* AC15(NC)* AC16(NC)* AC17(NC)* AC19(NC)* AC20(NC)* AC21(NC)* AC22(NC)* AC24(IO_2A_AC24/DIFFIO_TX_L28N/DIFFOUT_L56N)* AC29(CLK2P_DIFFIO_RX_L15P_DIFFOUT_L29P)* AC31(GXB_CMUTX_L0P)* AC32(GXB_CMUTX_L0N)* AD14(NC)* AD15(NC)* AD20(NC)* AD21(NC)* AD23(IO_2A_AD23/DIFFIO_TX_L28P/DIFFOUT_L56P)* AD24(IO_2A_AD24/DIFFIO_TX_L21N/DIFFOUT_L42N)* AE3(GXB_TX_R1N)* AE4(GXB_TX_R1P)* AE13(NC)* AE14(NC)* AE20(NC)* AE21(NC)* AE22(NC)* AE23(IO_2A_AE23/DIFFIO_TX_L21P/DIFFOUT_L42P)* AE31(GXB_TX_L1P) AE32(GXB_TX_L1N) AF13(NC)* AF24(IO_2A_AF24/DQ12L/DIFFIO_TX_L23N/DIFFOUT_L46N)* AF29(IO_2A_AF29/DIFFIO_RX_L21N/DIFFOUT_L41N)* AG3(GXB_TX_R0N)* AG4(GXB_TX_R0P)* AG29(IO_2A_AG29/DIFFIO_RX_L21P/DIFFOUT_L41P)* AG31(GXB_TX_L0P) AG32(GXB_TX_L0N) AH26(IO_2A_AH26/DQS11L/DIFFIO_RX_L23P/DIFFOUT_L45P)* AH29(IO_2A_AH29/DQSN12L/DIFFIO_RX_L24N/DIFFOUT_L47N)* AJ3(NC)* AJ4(NC)* AJ27(IO_2A_AJ27/DQSN11L/DIFFIO_RX_L23N/DIFFOUT_L45N)* AJ31(NC)* AJ32(NC)* AK3(NC)* AK32(NC)* AL4(NC)* AL30(NC)* AL31(NC)* AM4(NC)* AM29(IO_2A_AM29/DQS13L/DIFFIO_RX_L26P/DIFFOUT_L51P)* AM30(IO_2A_AM30/DQSN13L/DIFFIO_RX_L26N/DIFFOUT_L51N)* AM31(NC)* AM32(NC)* AN3(NC)* AN15(CLK6P_DIFFIO_RX_B17P_DIFFOUT_B33P)* AN17(CLK7P_DIFFOUT_B34P)* AN18(CLK4P_DIFFIO_RX_B16P_DIFFOUT_B32P)* AN32(NC)* AP2(NC)* AP3(NC)* AP15(CLK6N_DIFFIO_RX_B17N_DIFFOUT_B33N)* AP17(CLK7N_DIFFOUT_B34N)* AP18(CLK4N_DIFFIO_RX_B16N_DIFFOUT_B32N)* AP32(NC)* AP33(NC)* B17(CLK13P_DIFFOUT_T31P)* C4(NC)* C28(RUP1A/DIFFIO_RX_L1P/DIFFOUT_L2P)* C29(IO_1A_C29/DQS2L/DIFFIO_RX_L3P/DIFFOUT_L6P)* C30(IO_1A_C30/DQSN2L/DIFFIO_RX_L3N/DIFFOUT_L6N)* C31(NC)* D28(IO_1A_D28/DQS1L/DIFFIO_RX_L2P/DIFFOUT_L4P)* D29(RDN1A/DIFFIO_RX_L1N/DIFFOUT_L2N)* E3(GXB_TX_R7N)* E4(GXB_TX_R7P)* E26(NC)* E27(NC)* E29(IO_1A_E29/DQSN1L/DIFFIO_RX_L2N/DIFFOUT_L4N)* E31(GXB_TX_L7P) E32(GXB_TX_L7N) F26(IO_1A_F26/DQ4L/DIFFIO_RX_L7P/DIFFOUT_L14P)* F28(IO_1A_F28/DQ2L/DIFFIO_RX_L4P/DIFFOUT_L8P)* F29(IO_1A_F29/DQ2L/DIFFIO_RX_L4N/DIFFOUT_L8N)* G3(GXB_TX_R6N)* G4(GXB_TX_R6P)* G26(IO_1A_G26/DQS4L/DIFFIO_RX_L6P/DIFFOUT_L12P)* G27(IO_1A_G27/DQ4L/DIFFIO_RX_L7N/DIFFOUT_L14N)* G28(IO_1A_G28/DQS3L/DIFFIO_RX_L5P/DIFFOUT_L10P)* G29(IO_1A_G29/DQSN3L/DIFFIO_RX_L5N/DIFFOUT_L10N)* G31(GXB_TX_L6P) G32(GXB_TX_L6N) H23(NC)* H27(IO_1A_H27/DQSN4L/DIFFIO_RX_L6N/DIFFOUT_L12N)* H29(IO_1A_H29/DIFFIO_RX_L8P/DIFFOUT_L16P)* J3(GXB_CMUTX_R3N)* J4(GXB_CMUTX_R3P)* J12(NC)* J13(NC)* J14(NC)* J23(NC)* J28(IO_1C_J28/DQS5L/DIFFIO_RX_L9P/DIFFOUT_L18P)* J29(IO_1C_J29/DQSN5L/DIFFIO_RX_L9N/DIFFOUT_L18N)* J30(IO_1A_J30/DIFFIO_RX_L8N/DIFFOUT_L16N)* J31(GXB_CMUTX_L3P)* J32(GXB_CMUTX_L3N)* K12(NC)* K13(NC)* K14(NC)* K15(NC)* K20(NC)* K21(NC)* K22(NC)* K23(NC)* K28(IO_1C_K28/DQS7L/DIFFIO_RX_L12P/DIFFOUT_L24P/DATA7)* K29(IO_1C_K29/DQSN7L/DIFFIO_RX_L12N/DIFFOUT_L24N/DATA6)* L3(GXB_CMUTX_R2N)* L4(GXB_CMUTX_R2P)* L12(NC)* L14(NC)* L15(NC)* L20(NC)* L21(NC)* L26(IO_1C_L26/DQ5L/DIFFIO_RX_L10P/DIFFOUT_L20P)* L27(IO_1C_L27/DQ5L/DIFFIO_RX_L10N/DIFFOUT_L20N)* L31(GXB_CMUTX_L2P)* L32(GXB_CMUTX_L2N)* M13(NC)* M14(NC)* M15(NC)* M16(NC)* M17(NC)* M19(NC)* M20(NC)* N3(GXB_TX_R5N)* N4(GXB_TX_R5P)* N31(GXB_TX_L5P) N32(GXB_TX_L5N) R3(GXB_TX_R4N)* R4(GXB_TX_R4P)* R31(GXB_TX_L4P) R32(GXB_TX_L4N) T26(CLK0N_DIFFIO_RX_L14N_DIFFOUT_L28N)* U3(GXB_TX_R3N)* U4(GXB_TX_R3P)* U26(CLK0P_DIFFIO_RX_L14P_DIFFOUT_L28P)* U31(GXB_TX_L3P) U32(GXB_TX_L3N) V17(DNU)* W3(GXB_TX_R2N)* W4(GXB_TX_R2P)* W31(GXB_TX_L2P) W32(GXB_TX_L2N)

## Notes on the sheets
sheet 2
- Buttons & Switches
- LEDs
- MECHANICAL PARTS
sheet 3
- ADC Interface
- CMOS Header
sheet 4
- DAC Interface
sheet 5
- USB
sheet 6
- DDR2 SO-DIMM
- Place near the DDR2 SO-DIMM
sheet 7
- BANK QL
sheet 8
- BANK1
- 2.5V
sheet 9
- BANK2
- 1.8V
- 2.5V
